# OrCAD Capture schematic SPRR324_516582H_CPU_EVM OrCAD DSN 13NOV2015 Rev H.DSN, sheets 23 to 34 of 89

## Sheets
23 SH29 - VAYU VIDEO PORTS IN: size B; rev: A
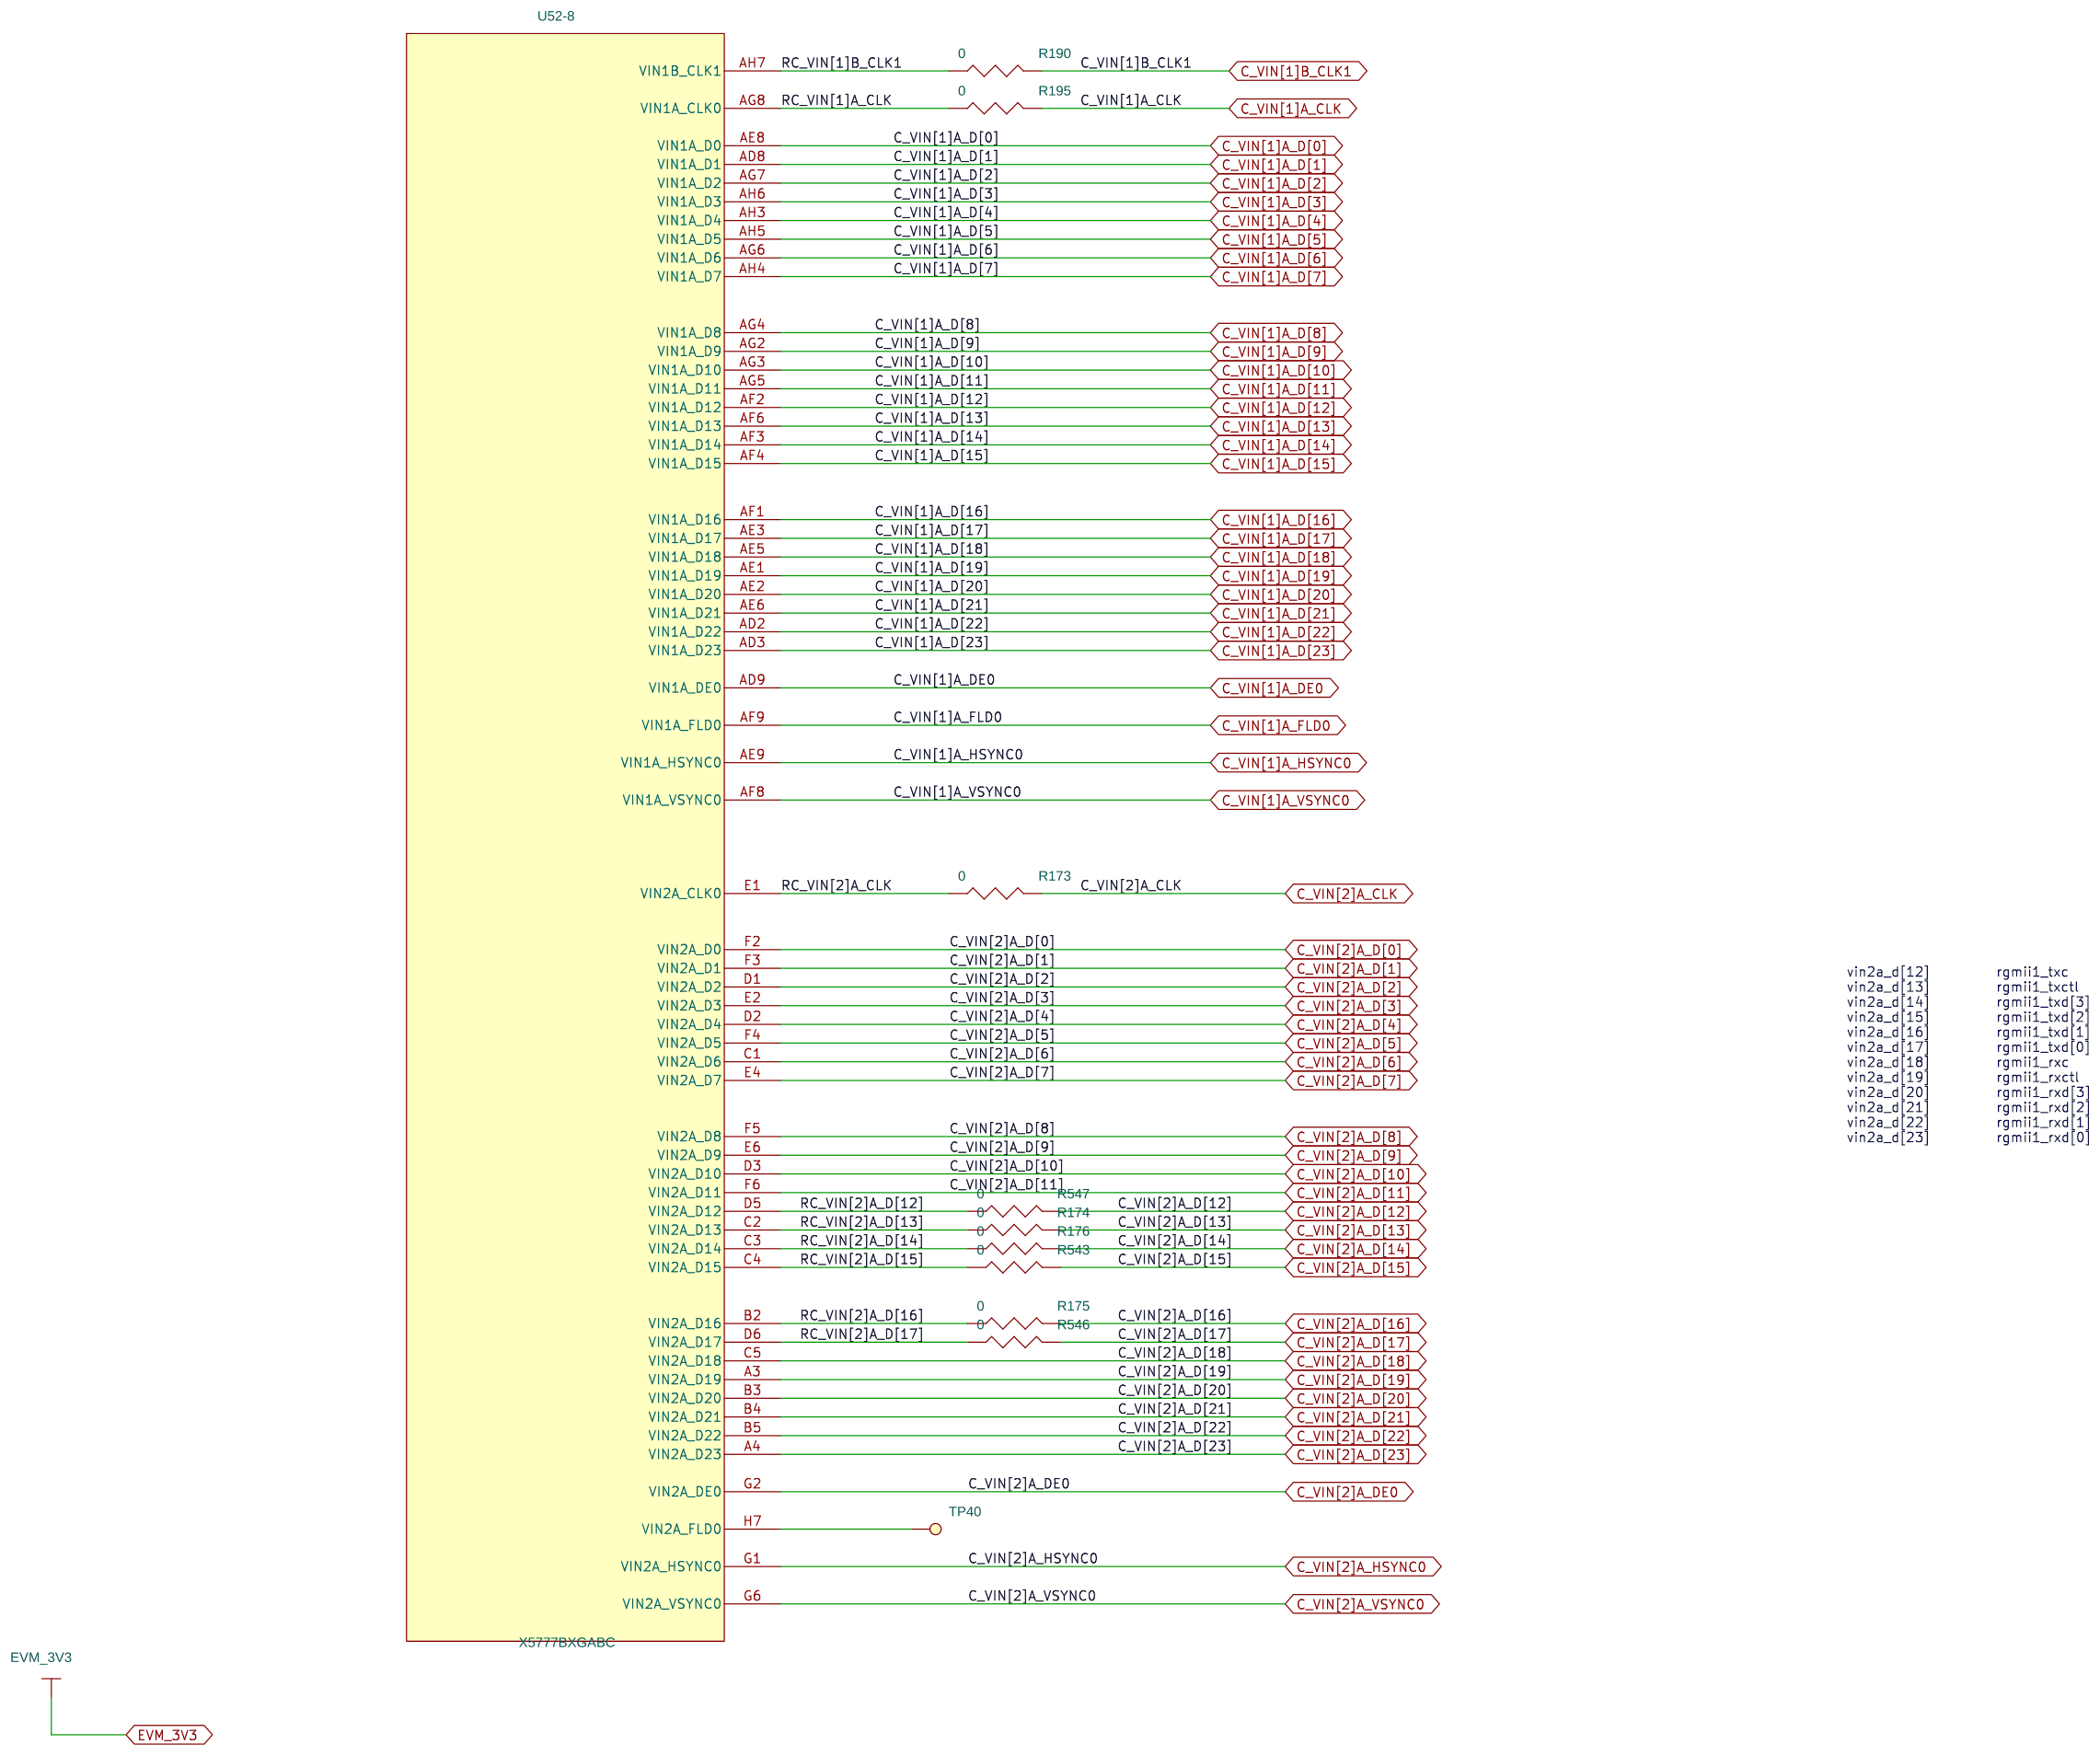
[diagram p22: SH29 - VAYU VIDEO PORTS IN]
24 SH30 - VIN1 MUX: size B; rev: A
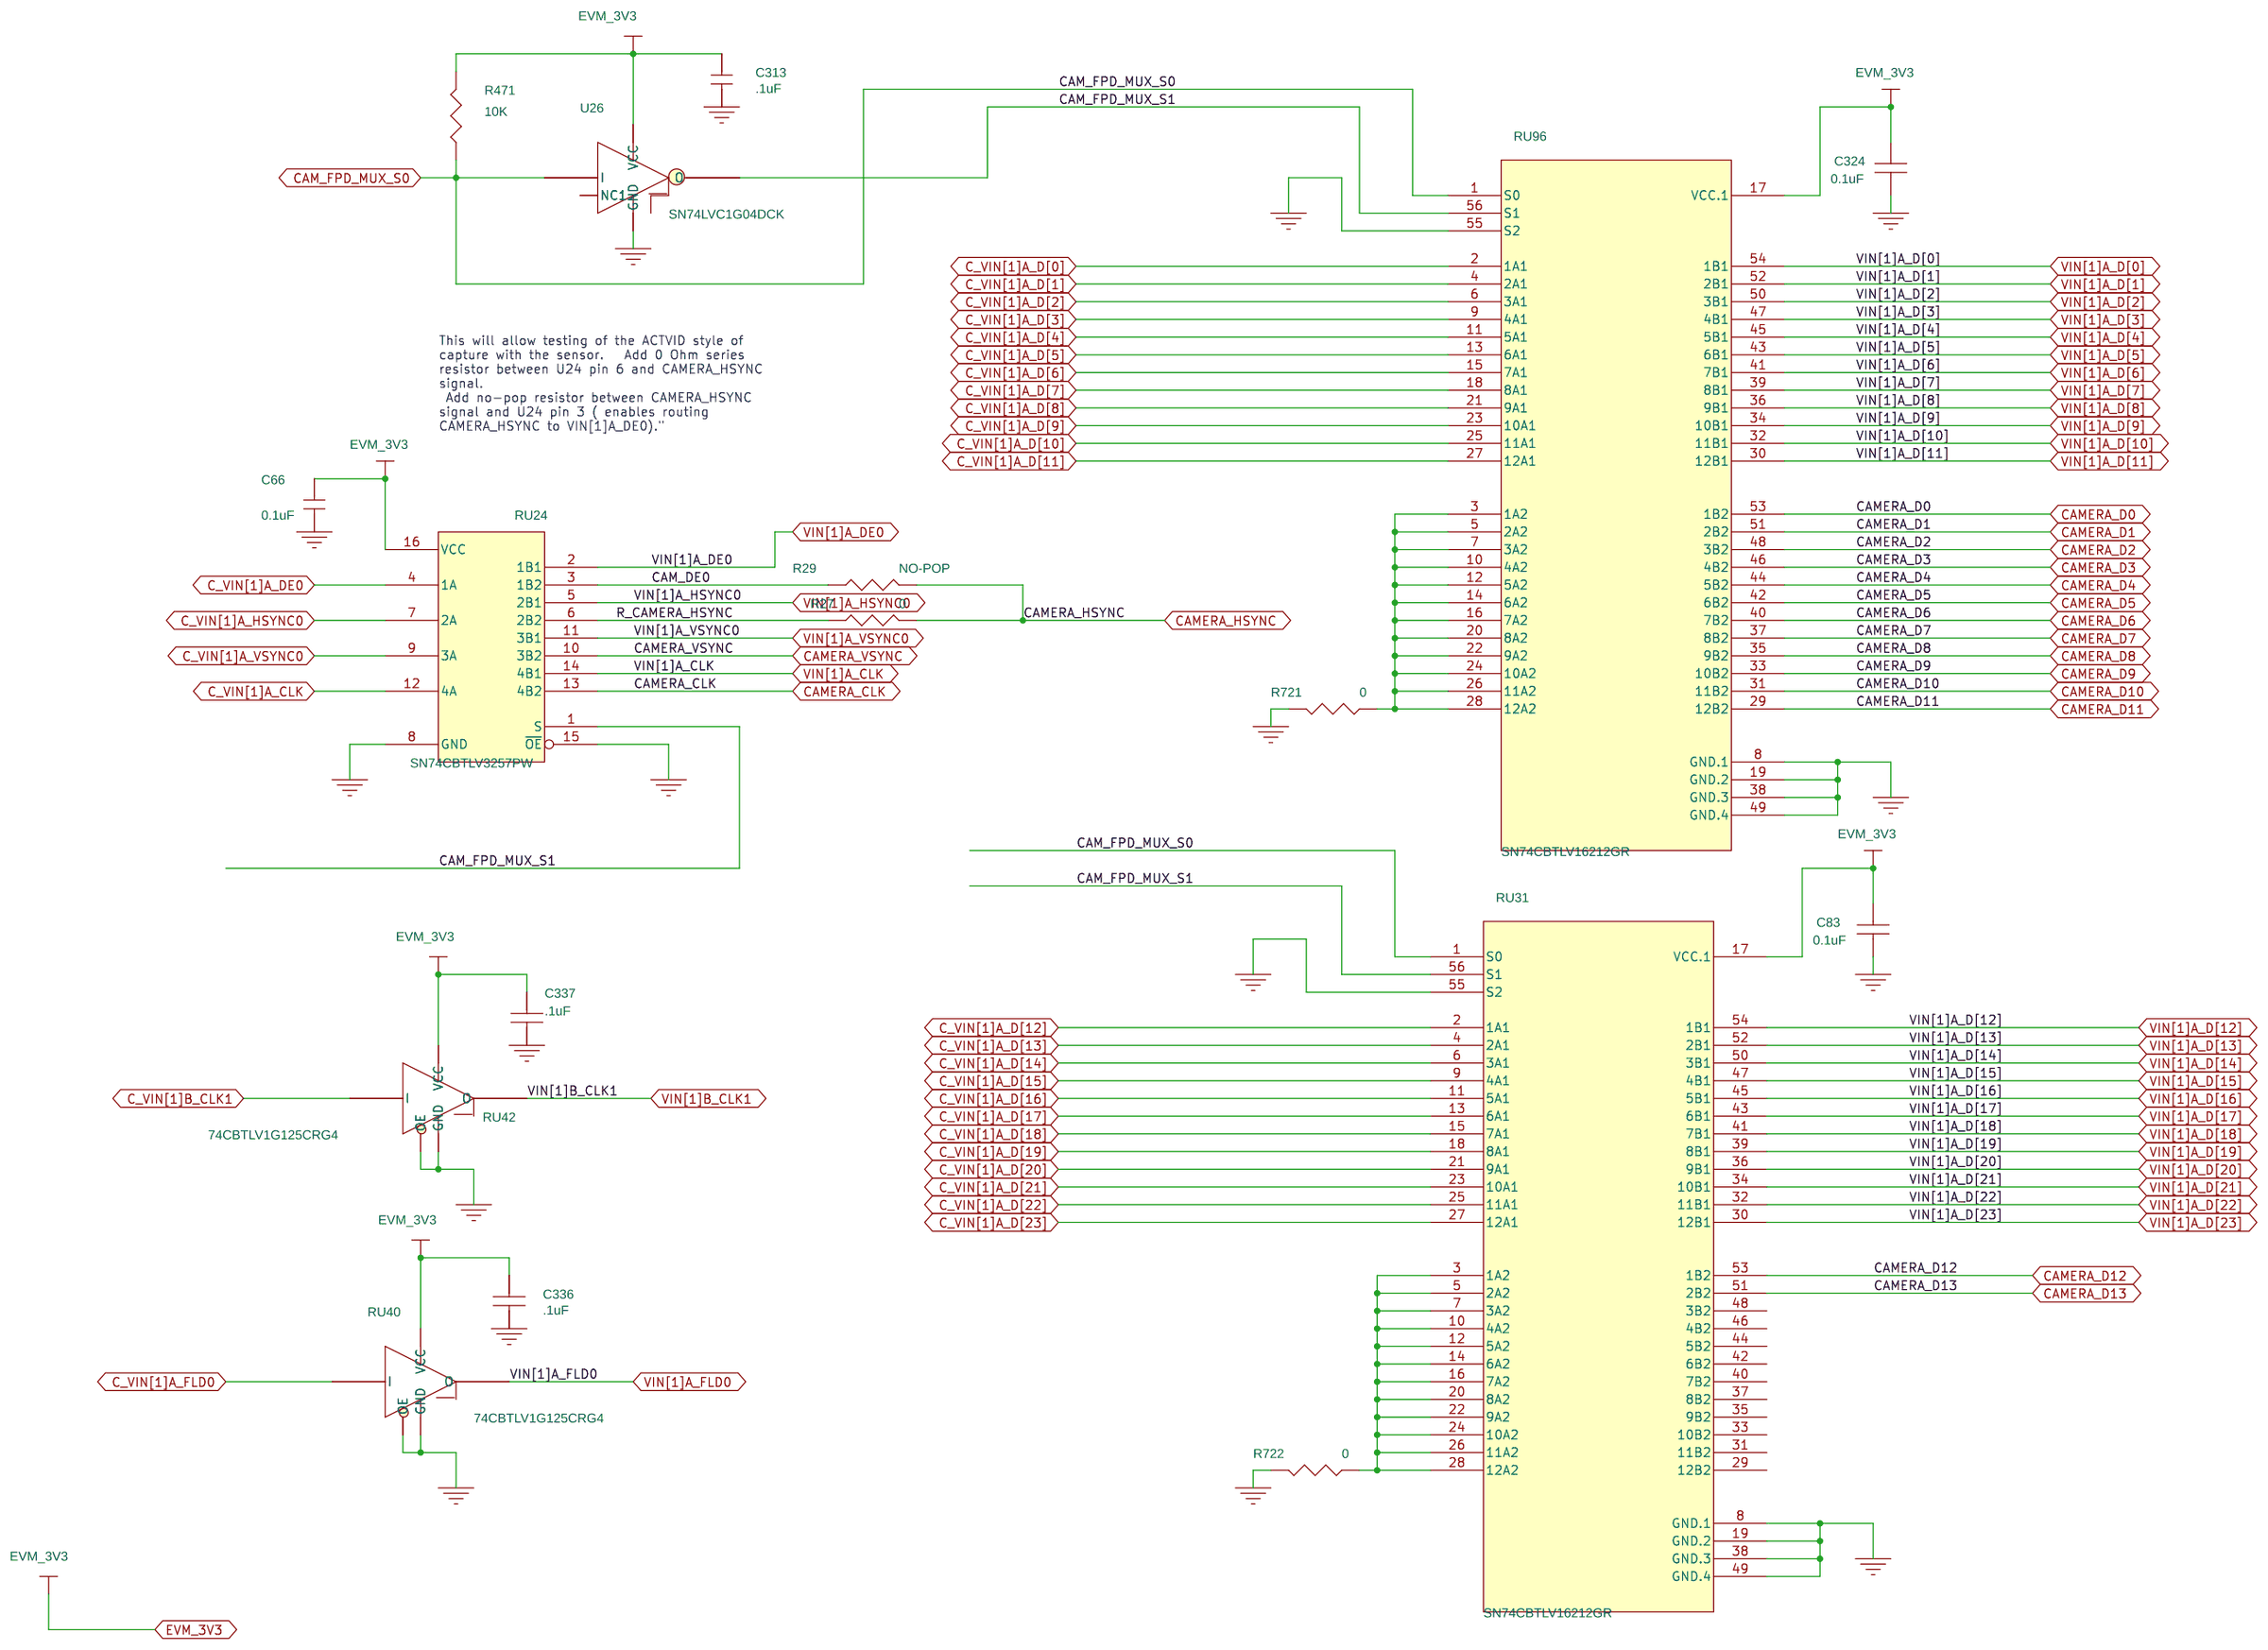
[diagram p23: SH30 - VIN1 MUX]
25 SH31 - VIN2 MUX: size B; rev: C
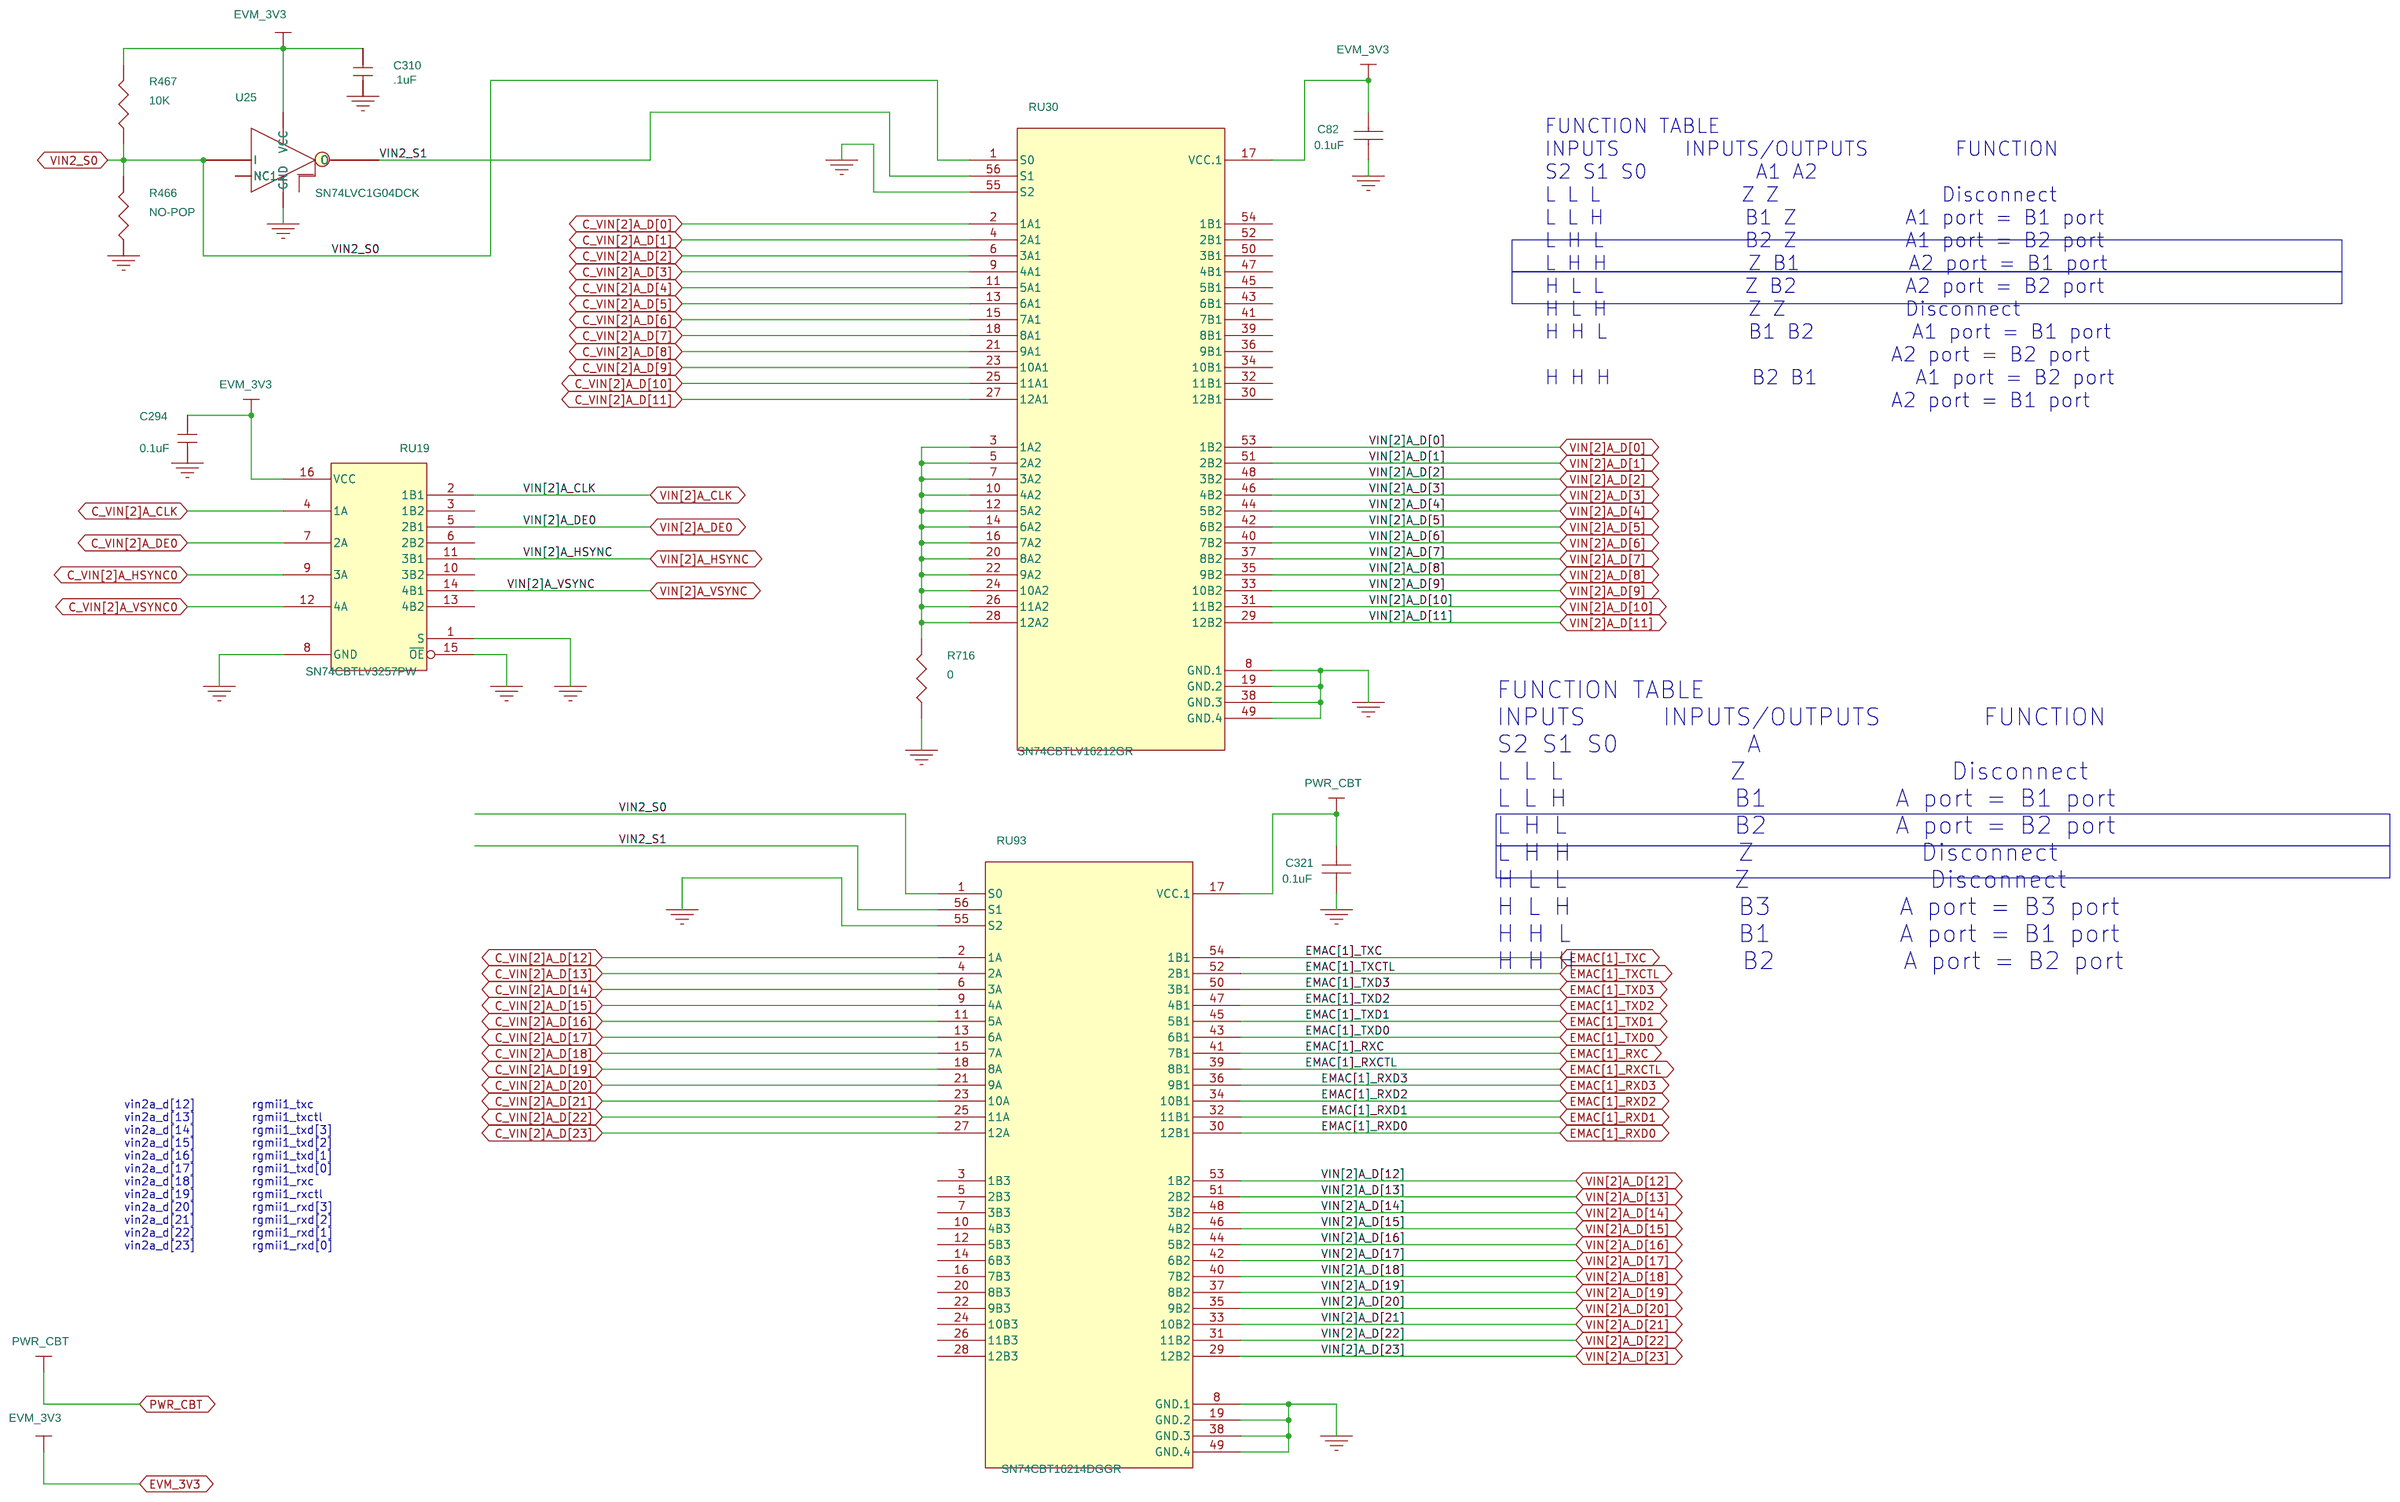
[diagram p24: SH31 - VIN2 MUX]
26 SH32 - LCD CONNECTOR: size B; rev: A
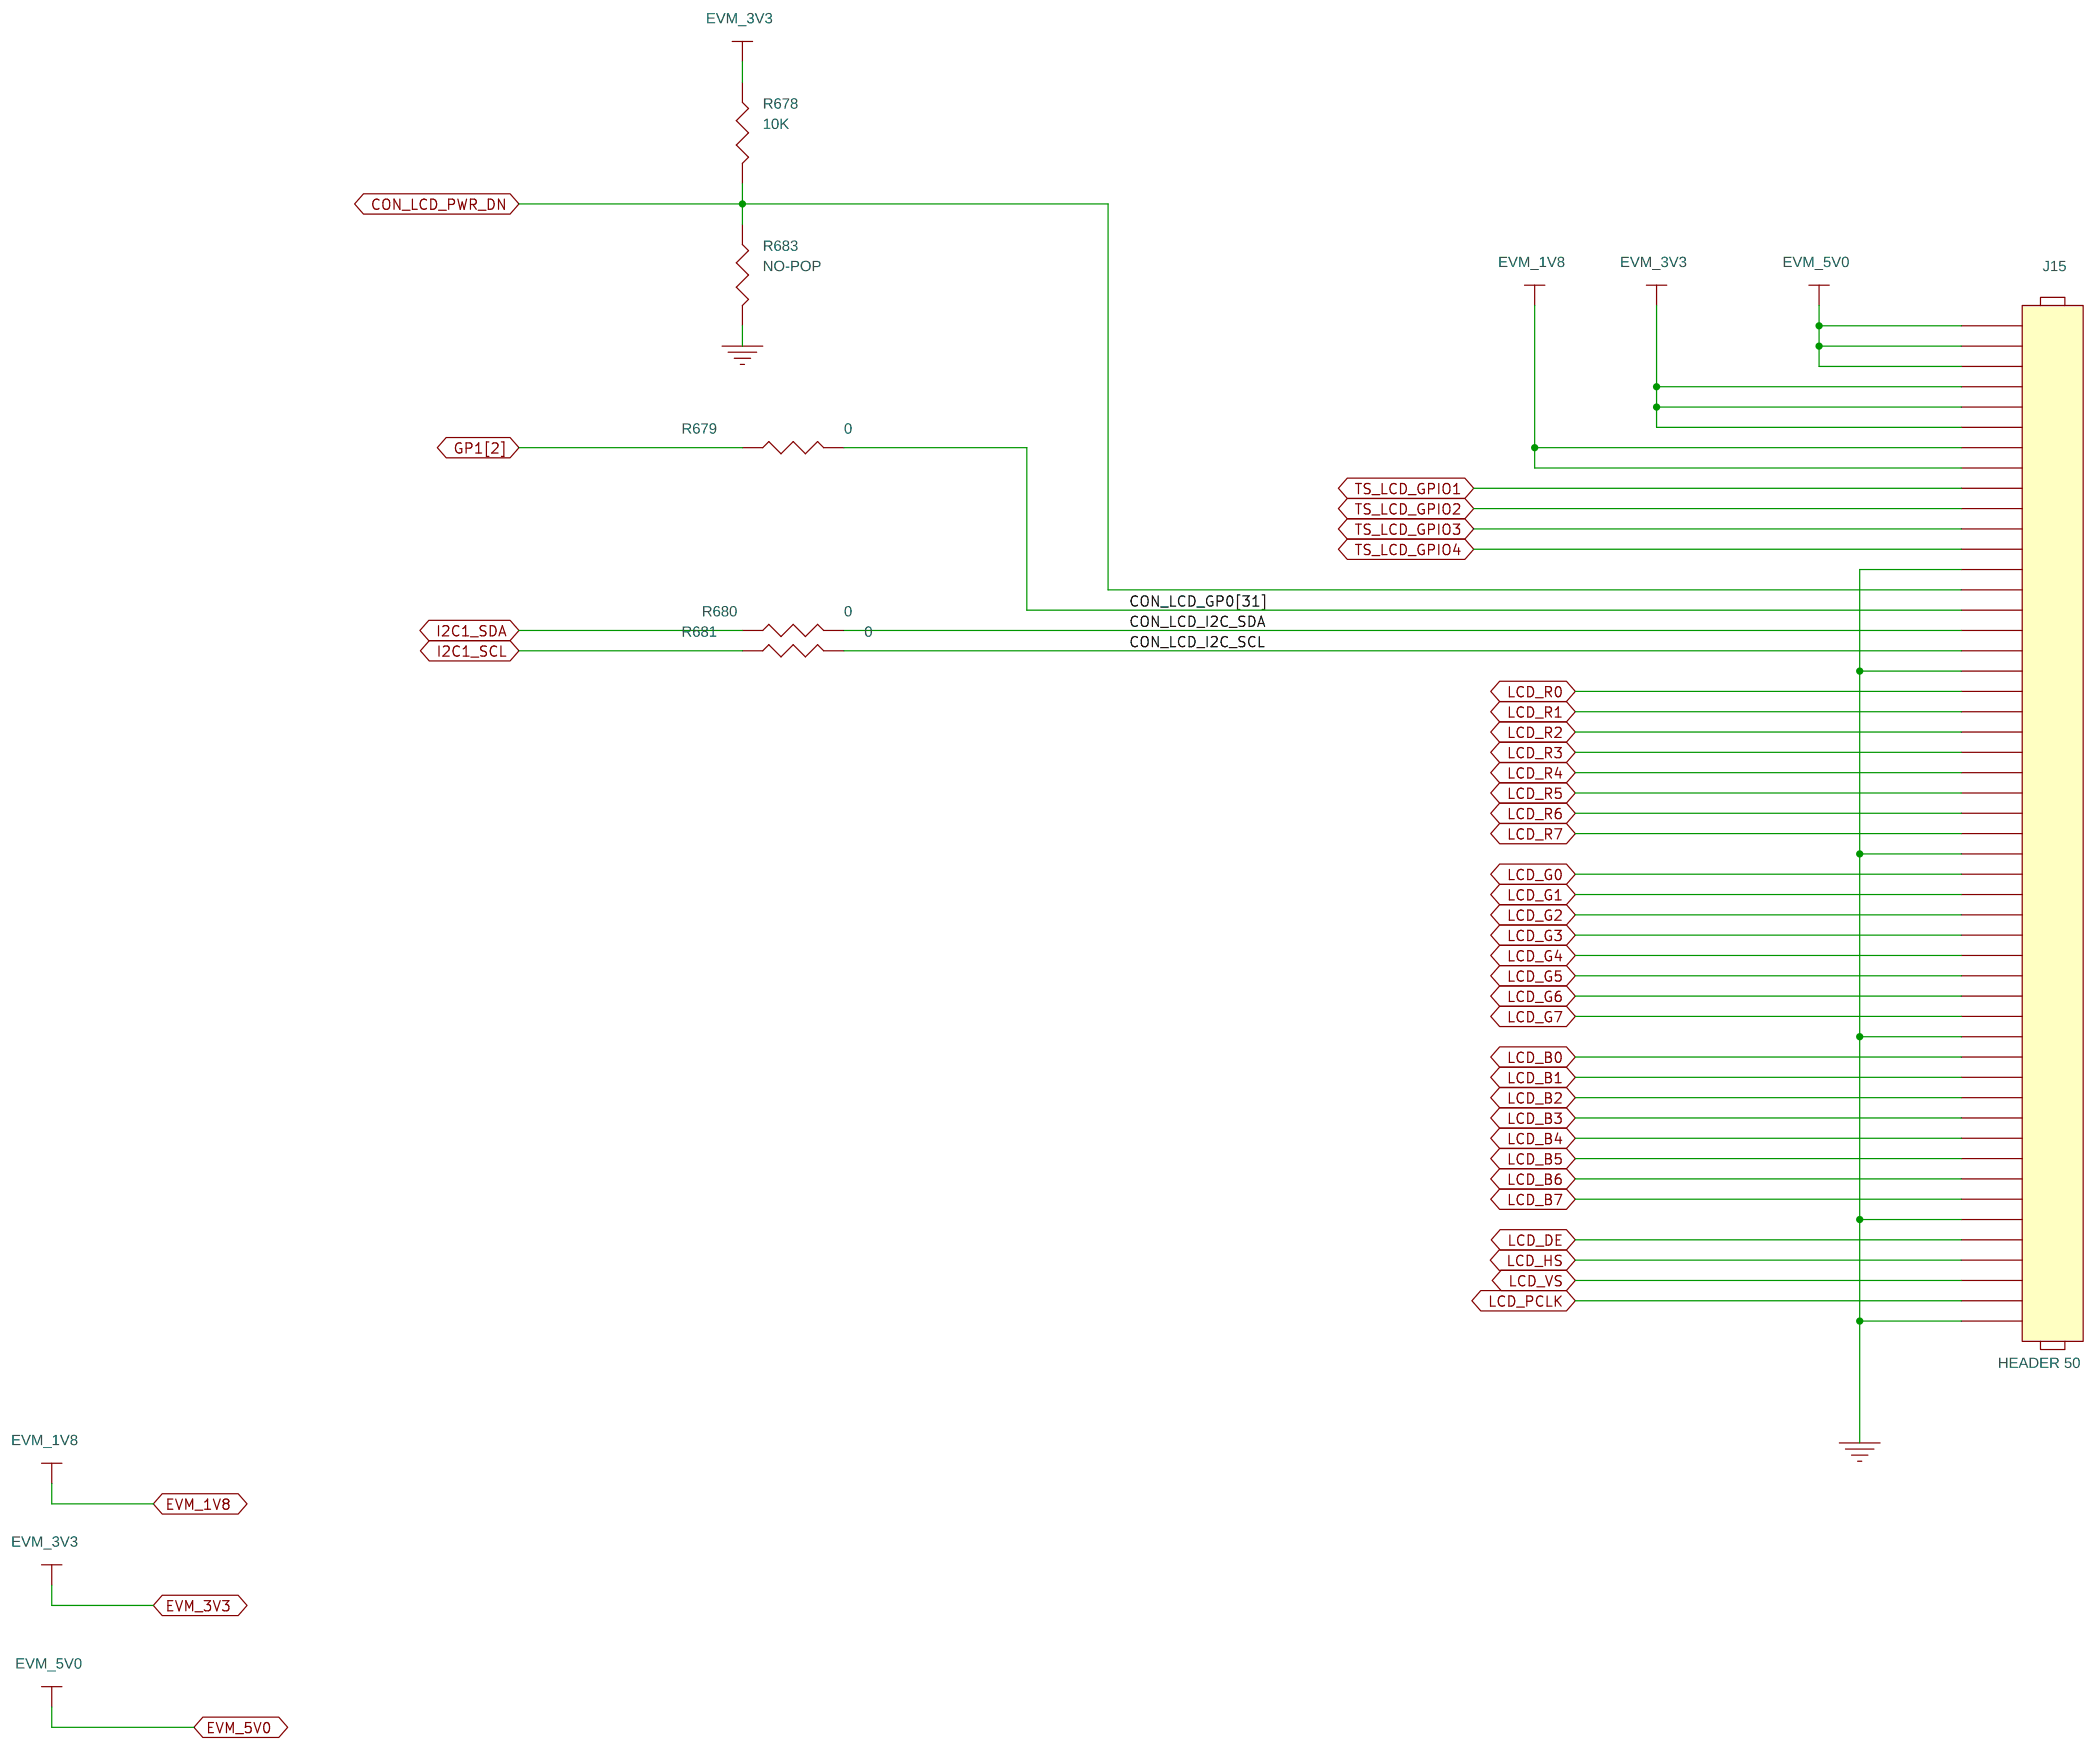
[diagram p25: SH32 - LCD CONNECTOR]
27 SH33 - HDMI OUTPUT CONNECTOR: size B
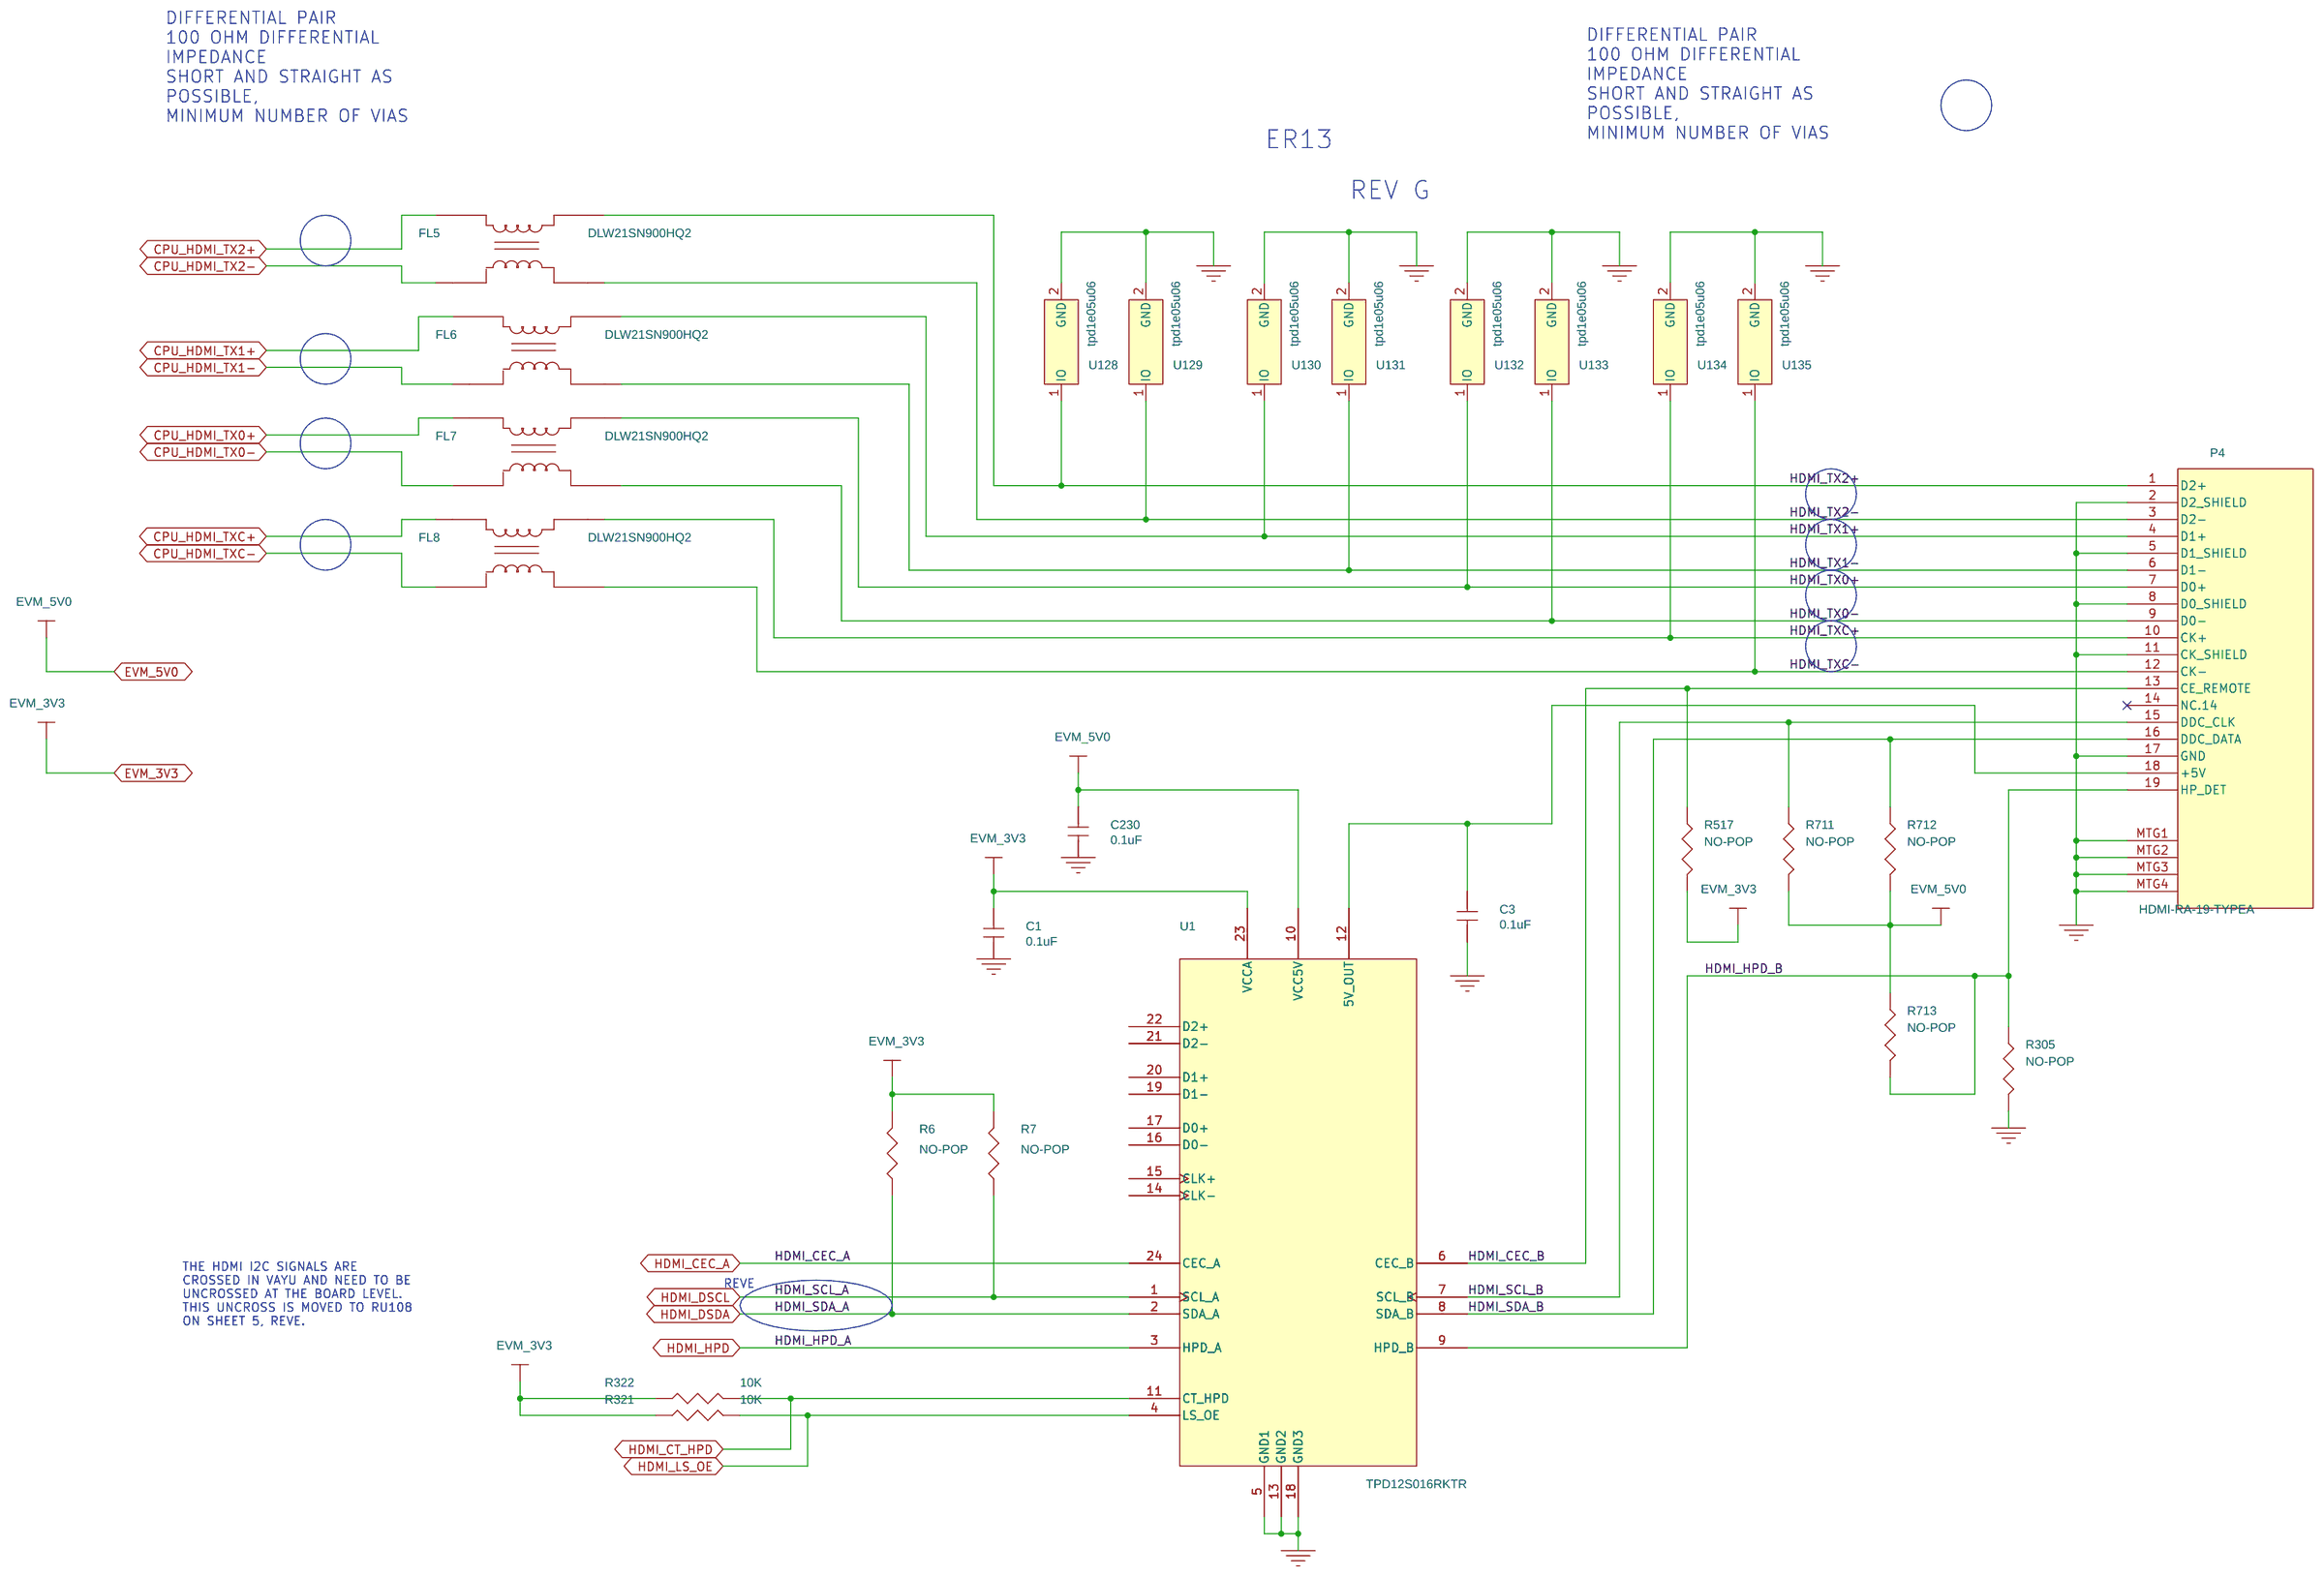
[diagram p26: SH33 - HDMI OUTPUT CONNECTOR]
28 SH34 - FPD LINK: size B; rev: E
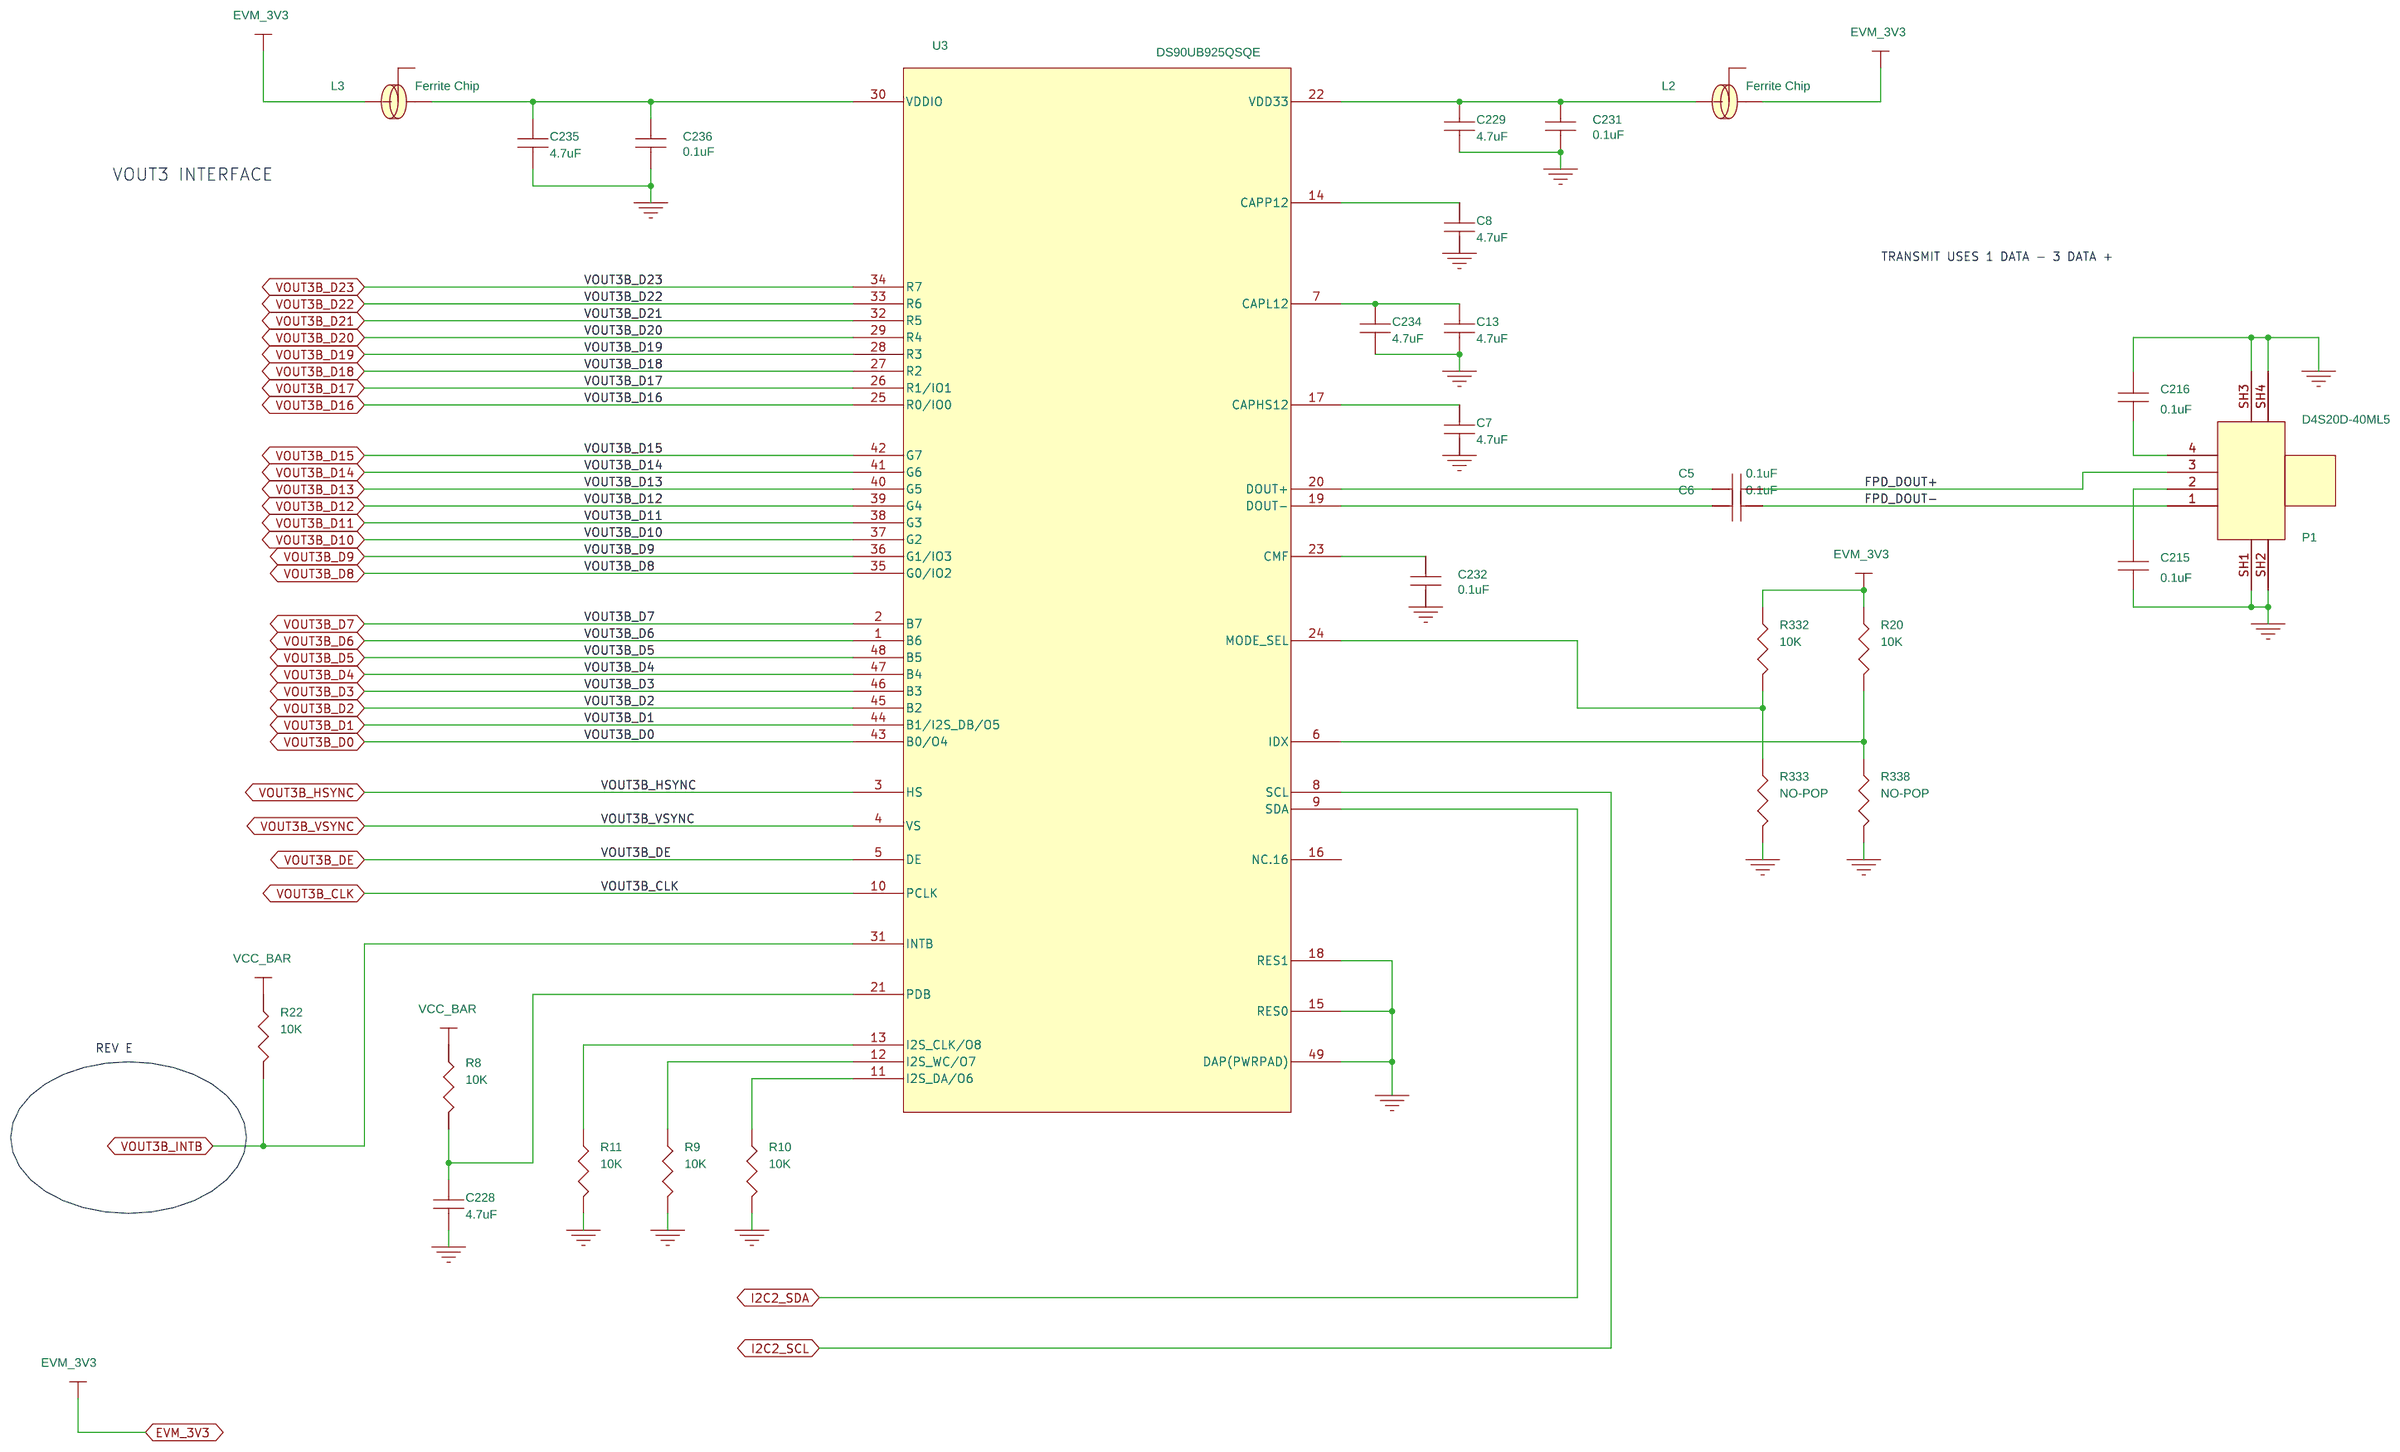
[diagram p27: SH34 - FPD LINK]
29 SH35 - CAMERA IF: size B; rev: G
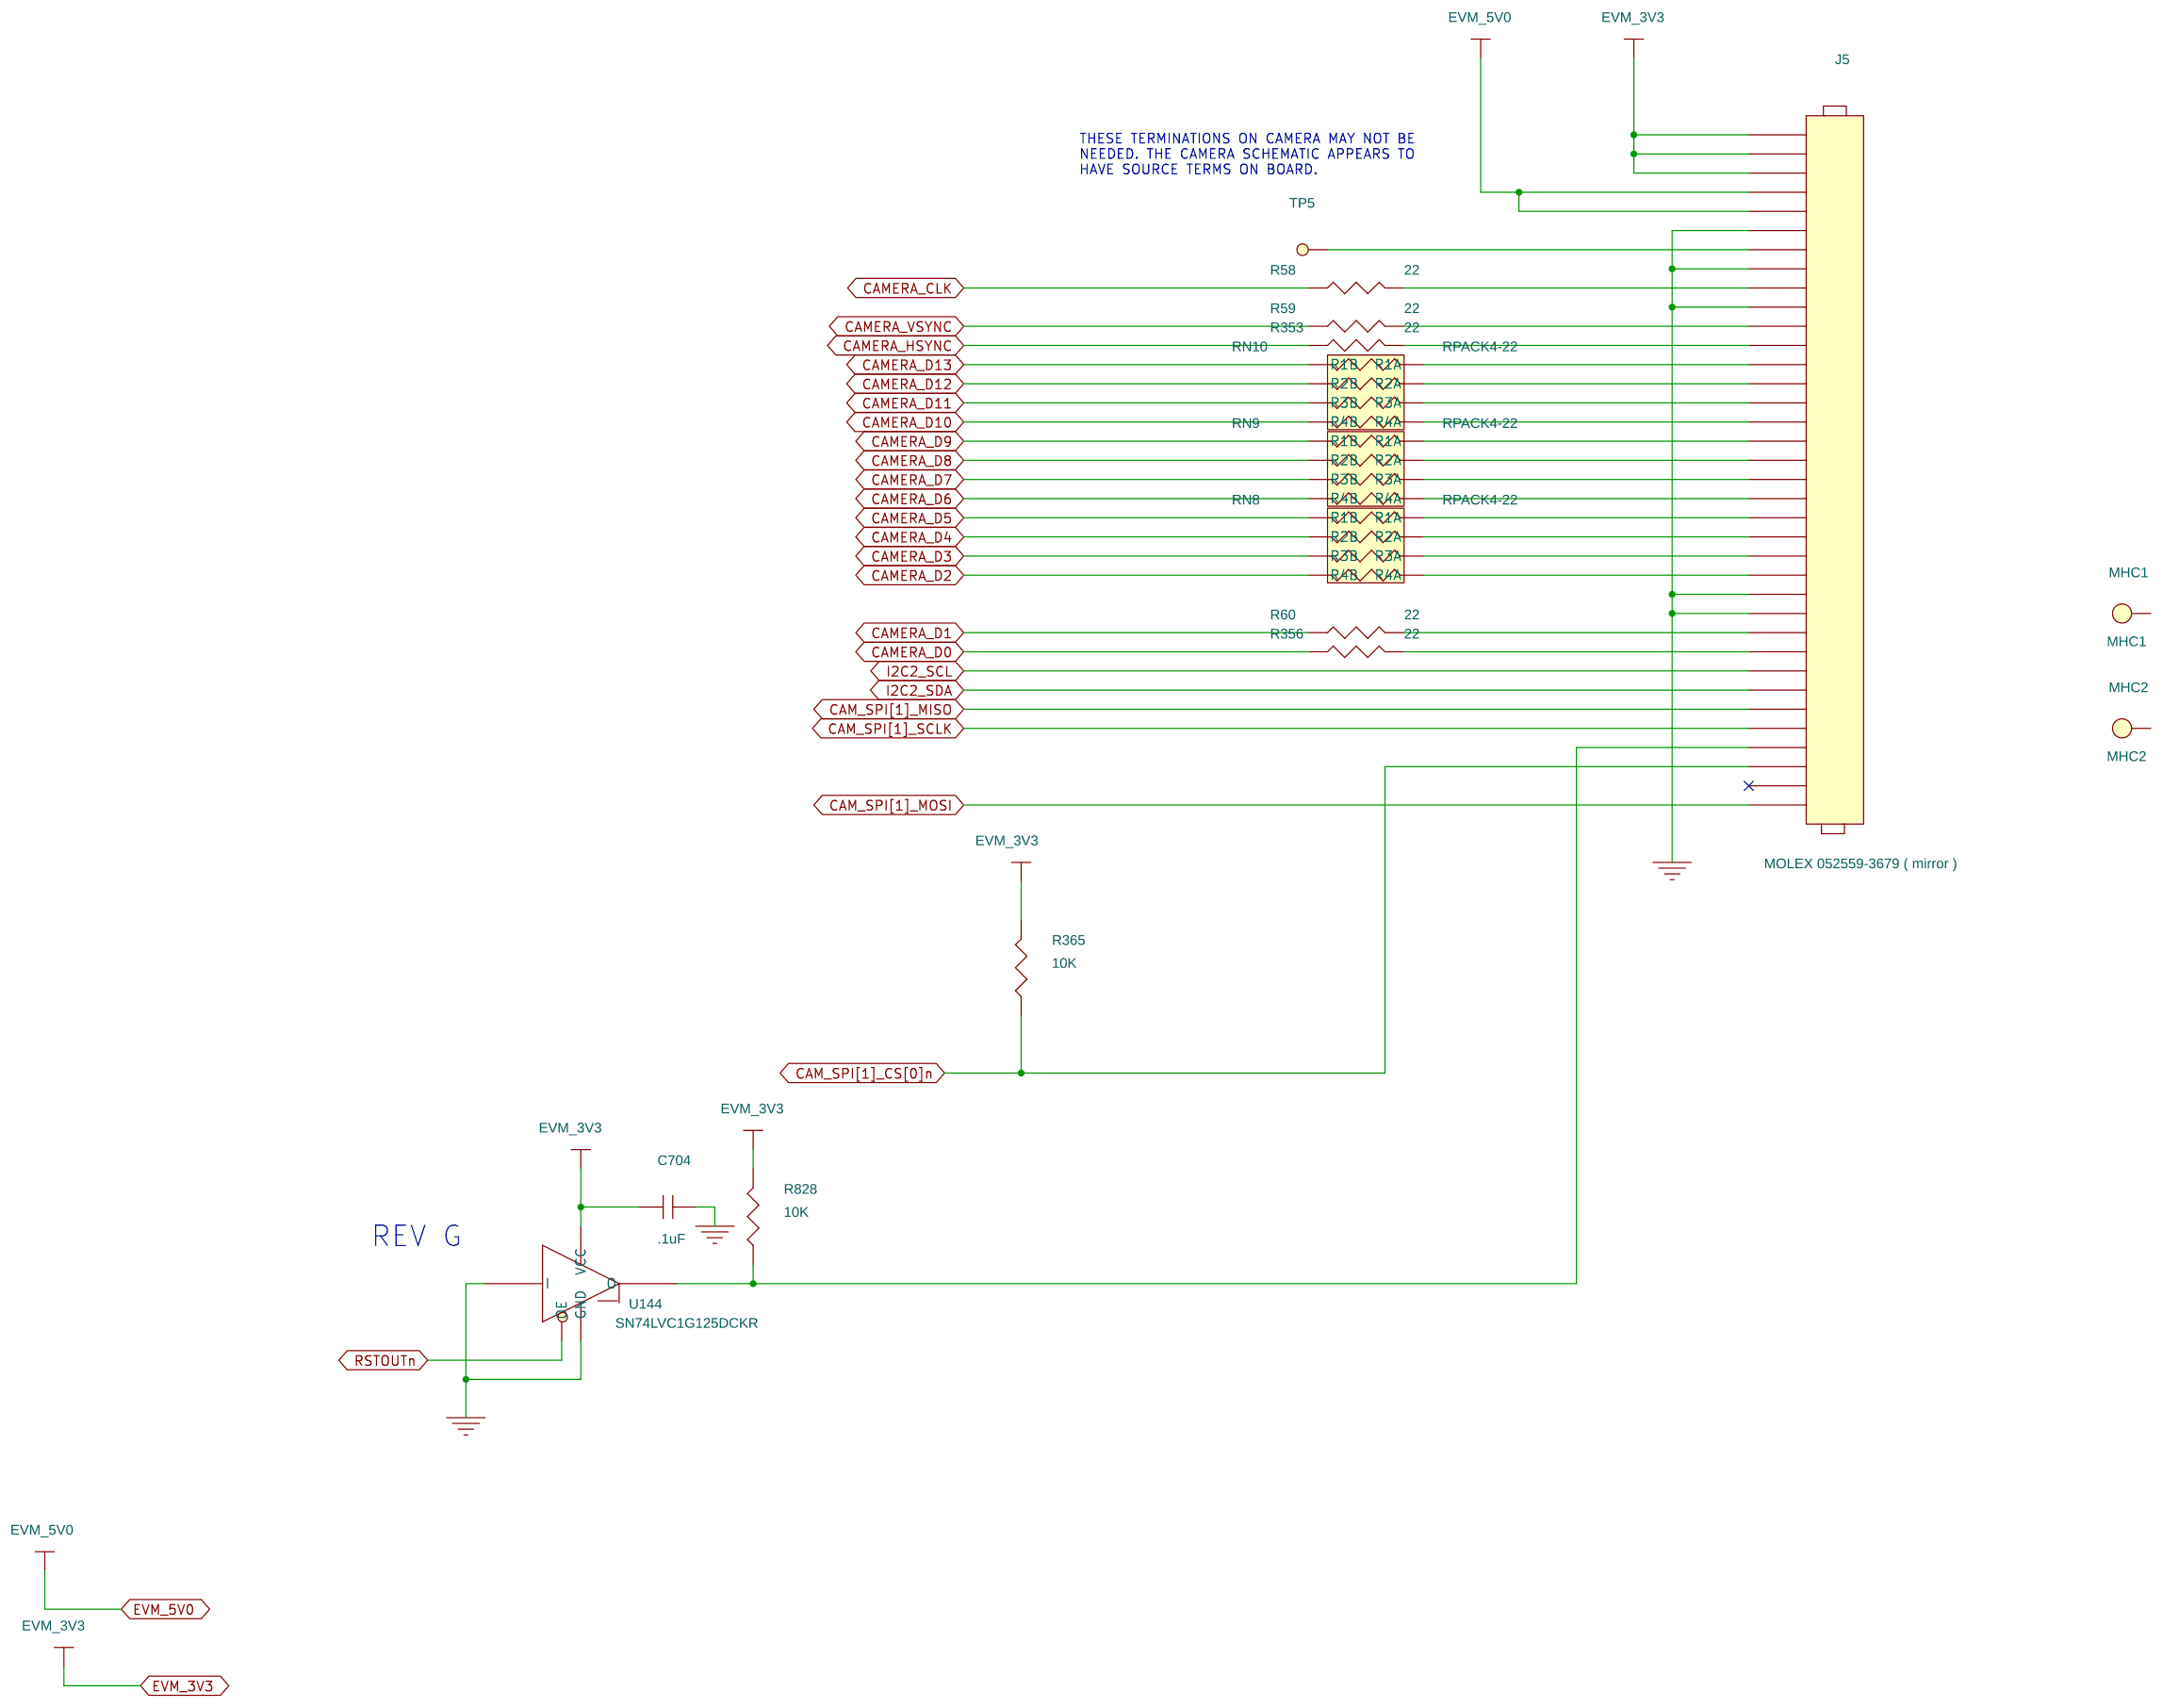
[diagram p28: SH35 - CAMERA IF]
30 SH36 - SERDES CLOCK: size B; rev: A
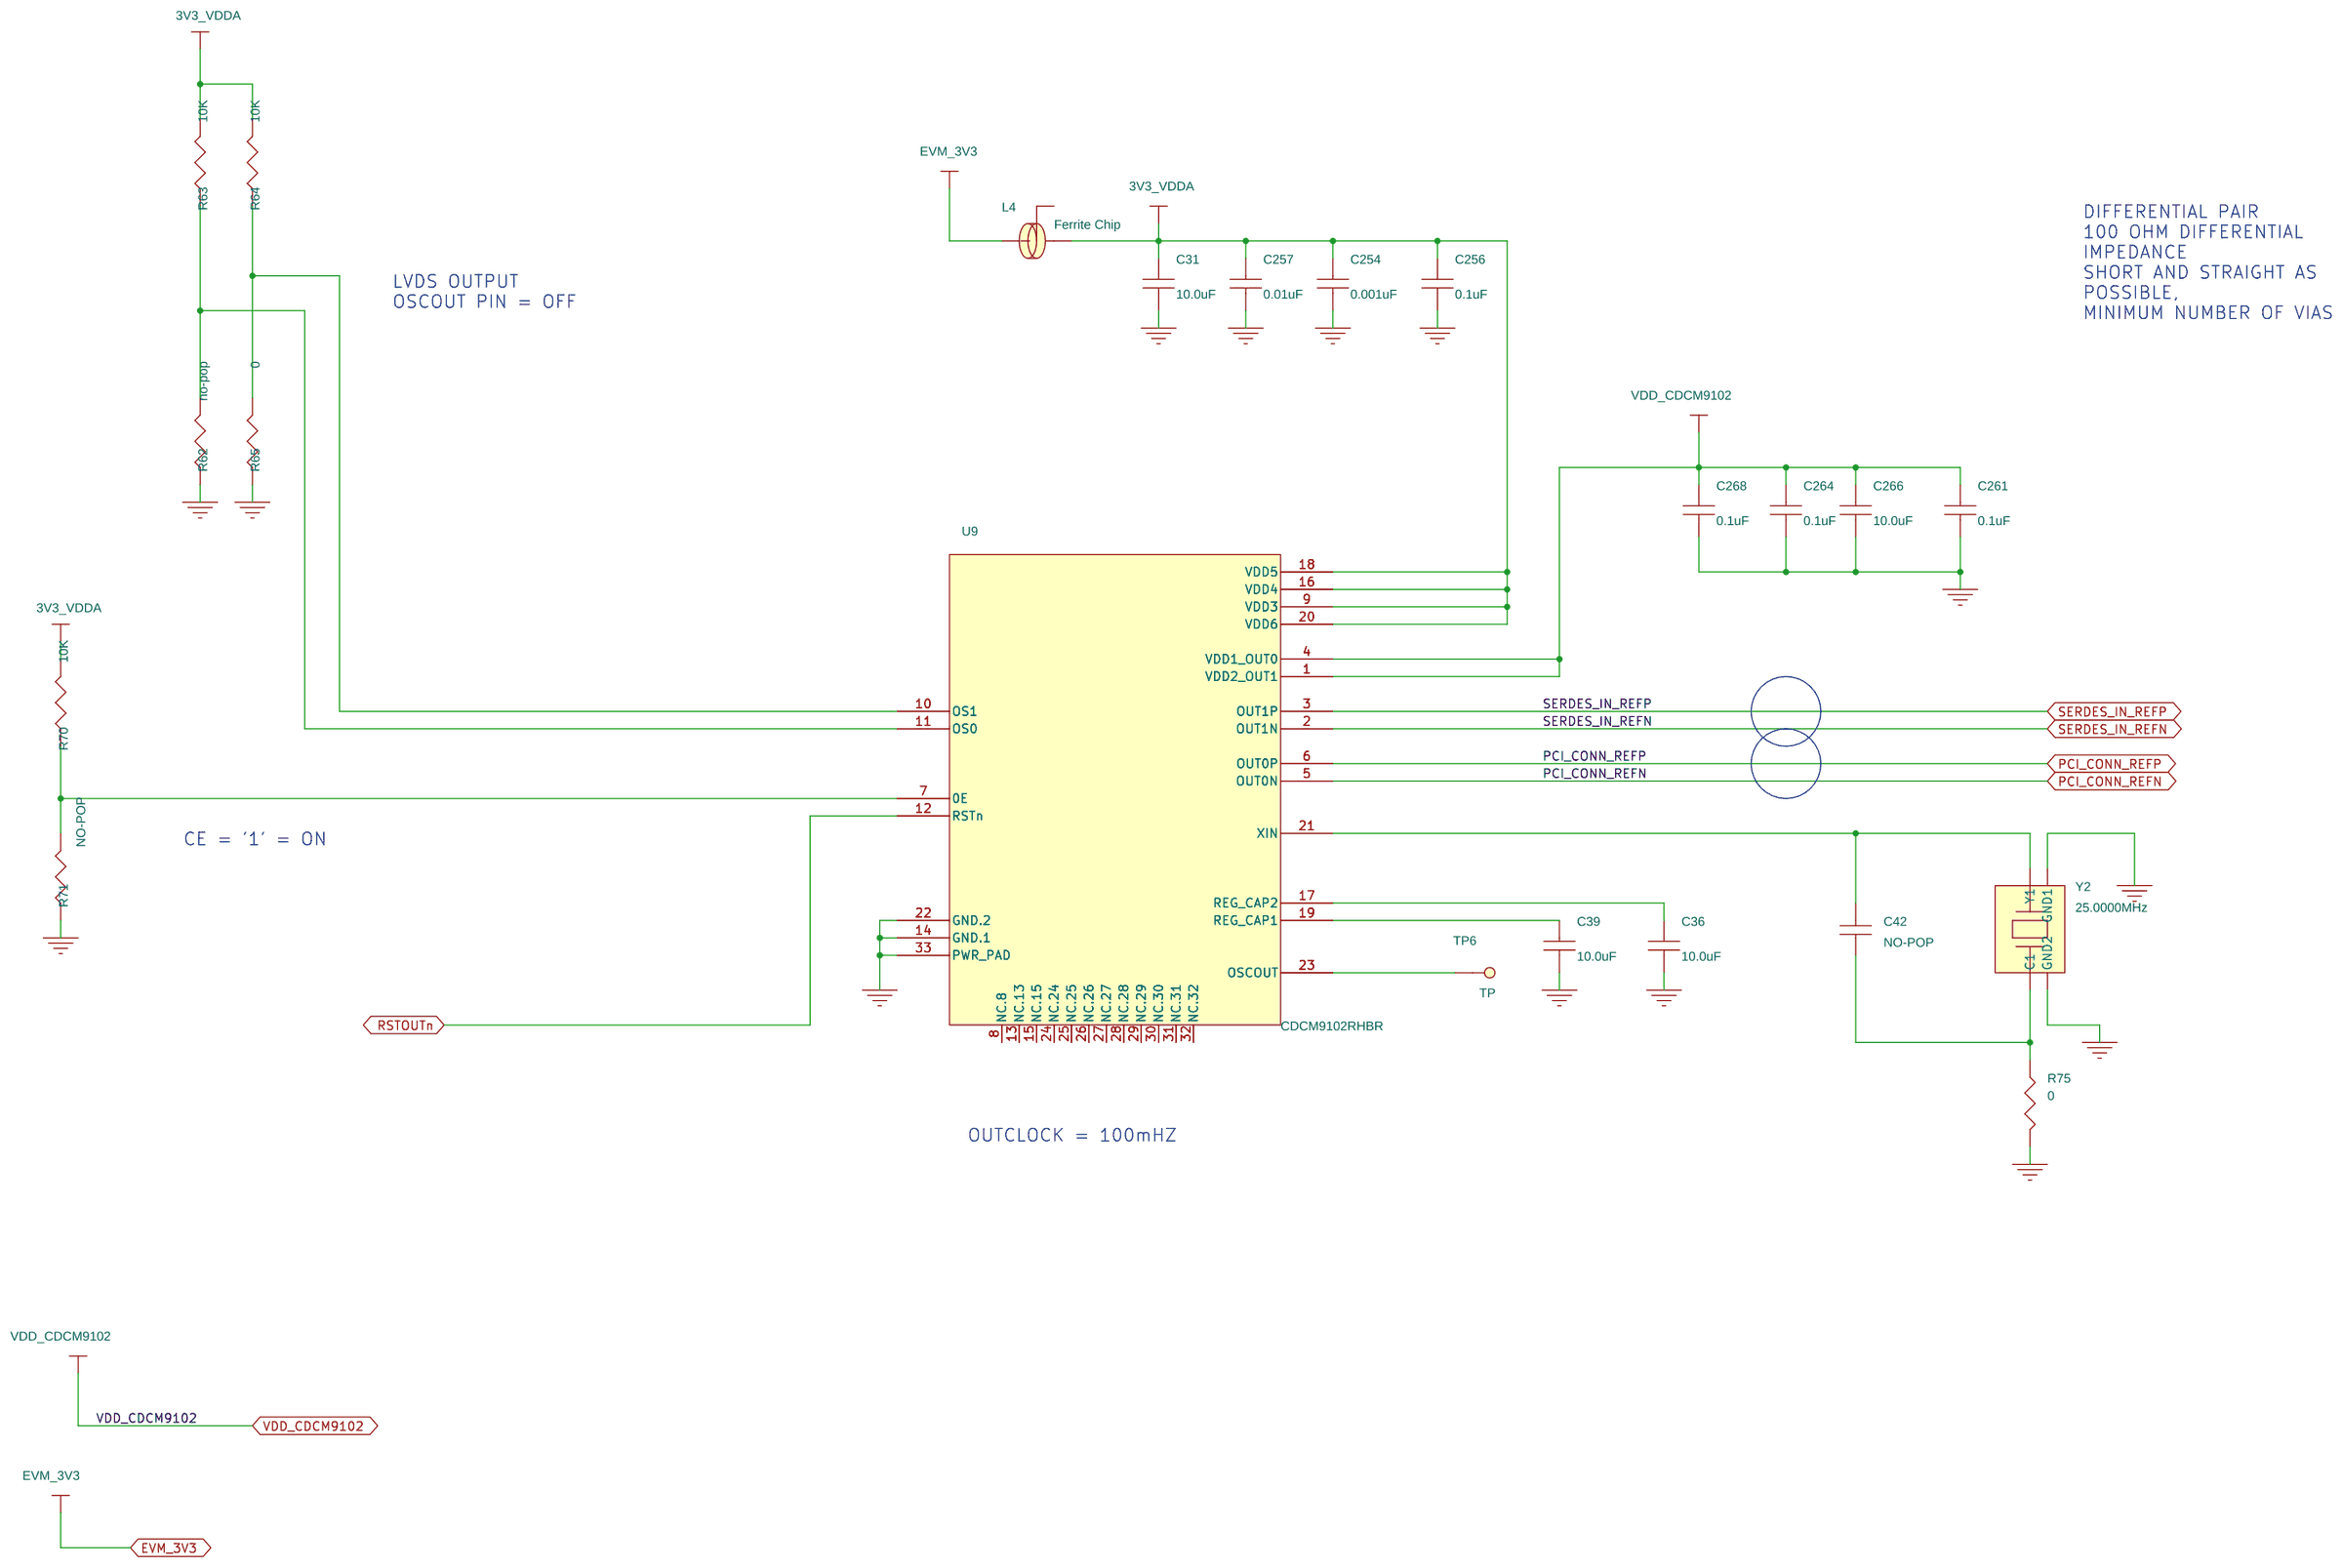
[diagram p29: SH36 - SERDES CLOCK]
31 SH38 - PCIe CONNECTORS: size B; rev: A
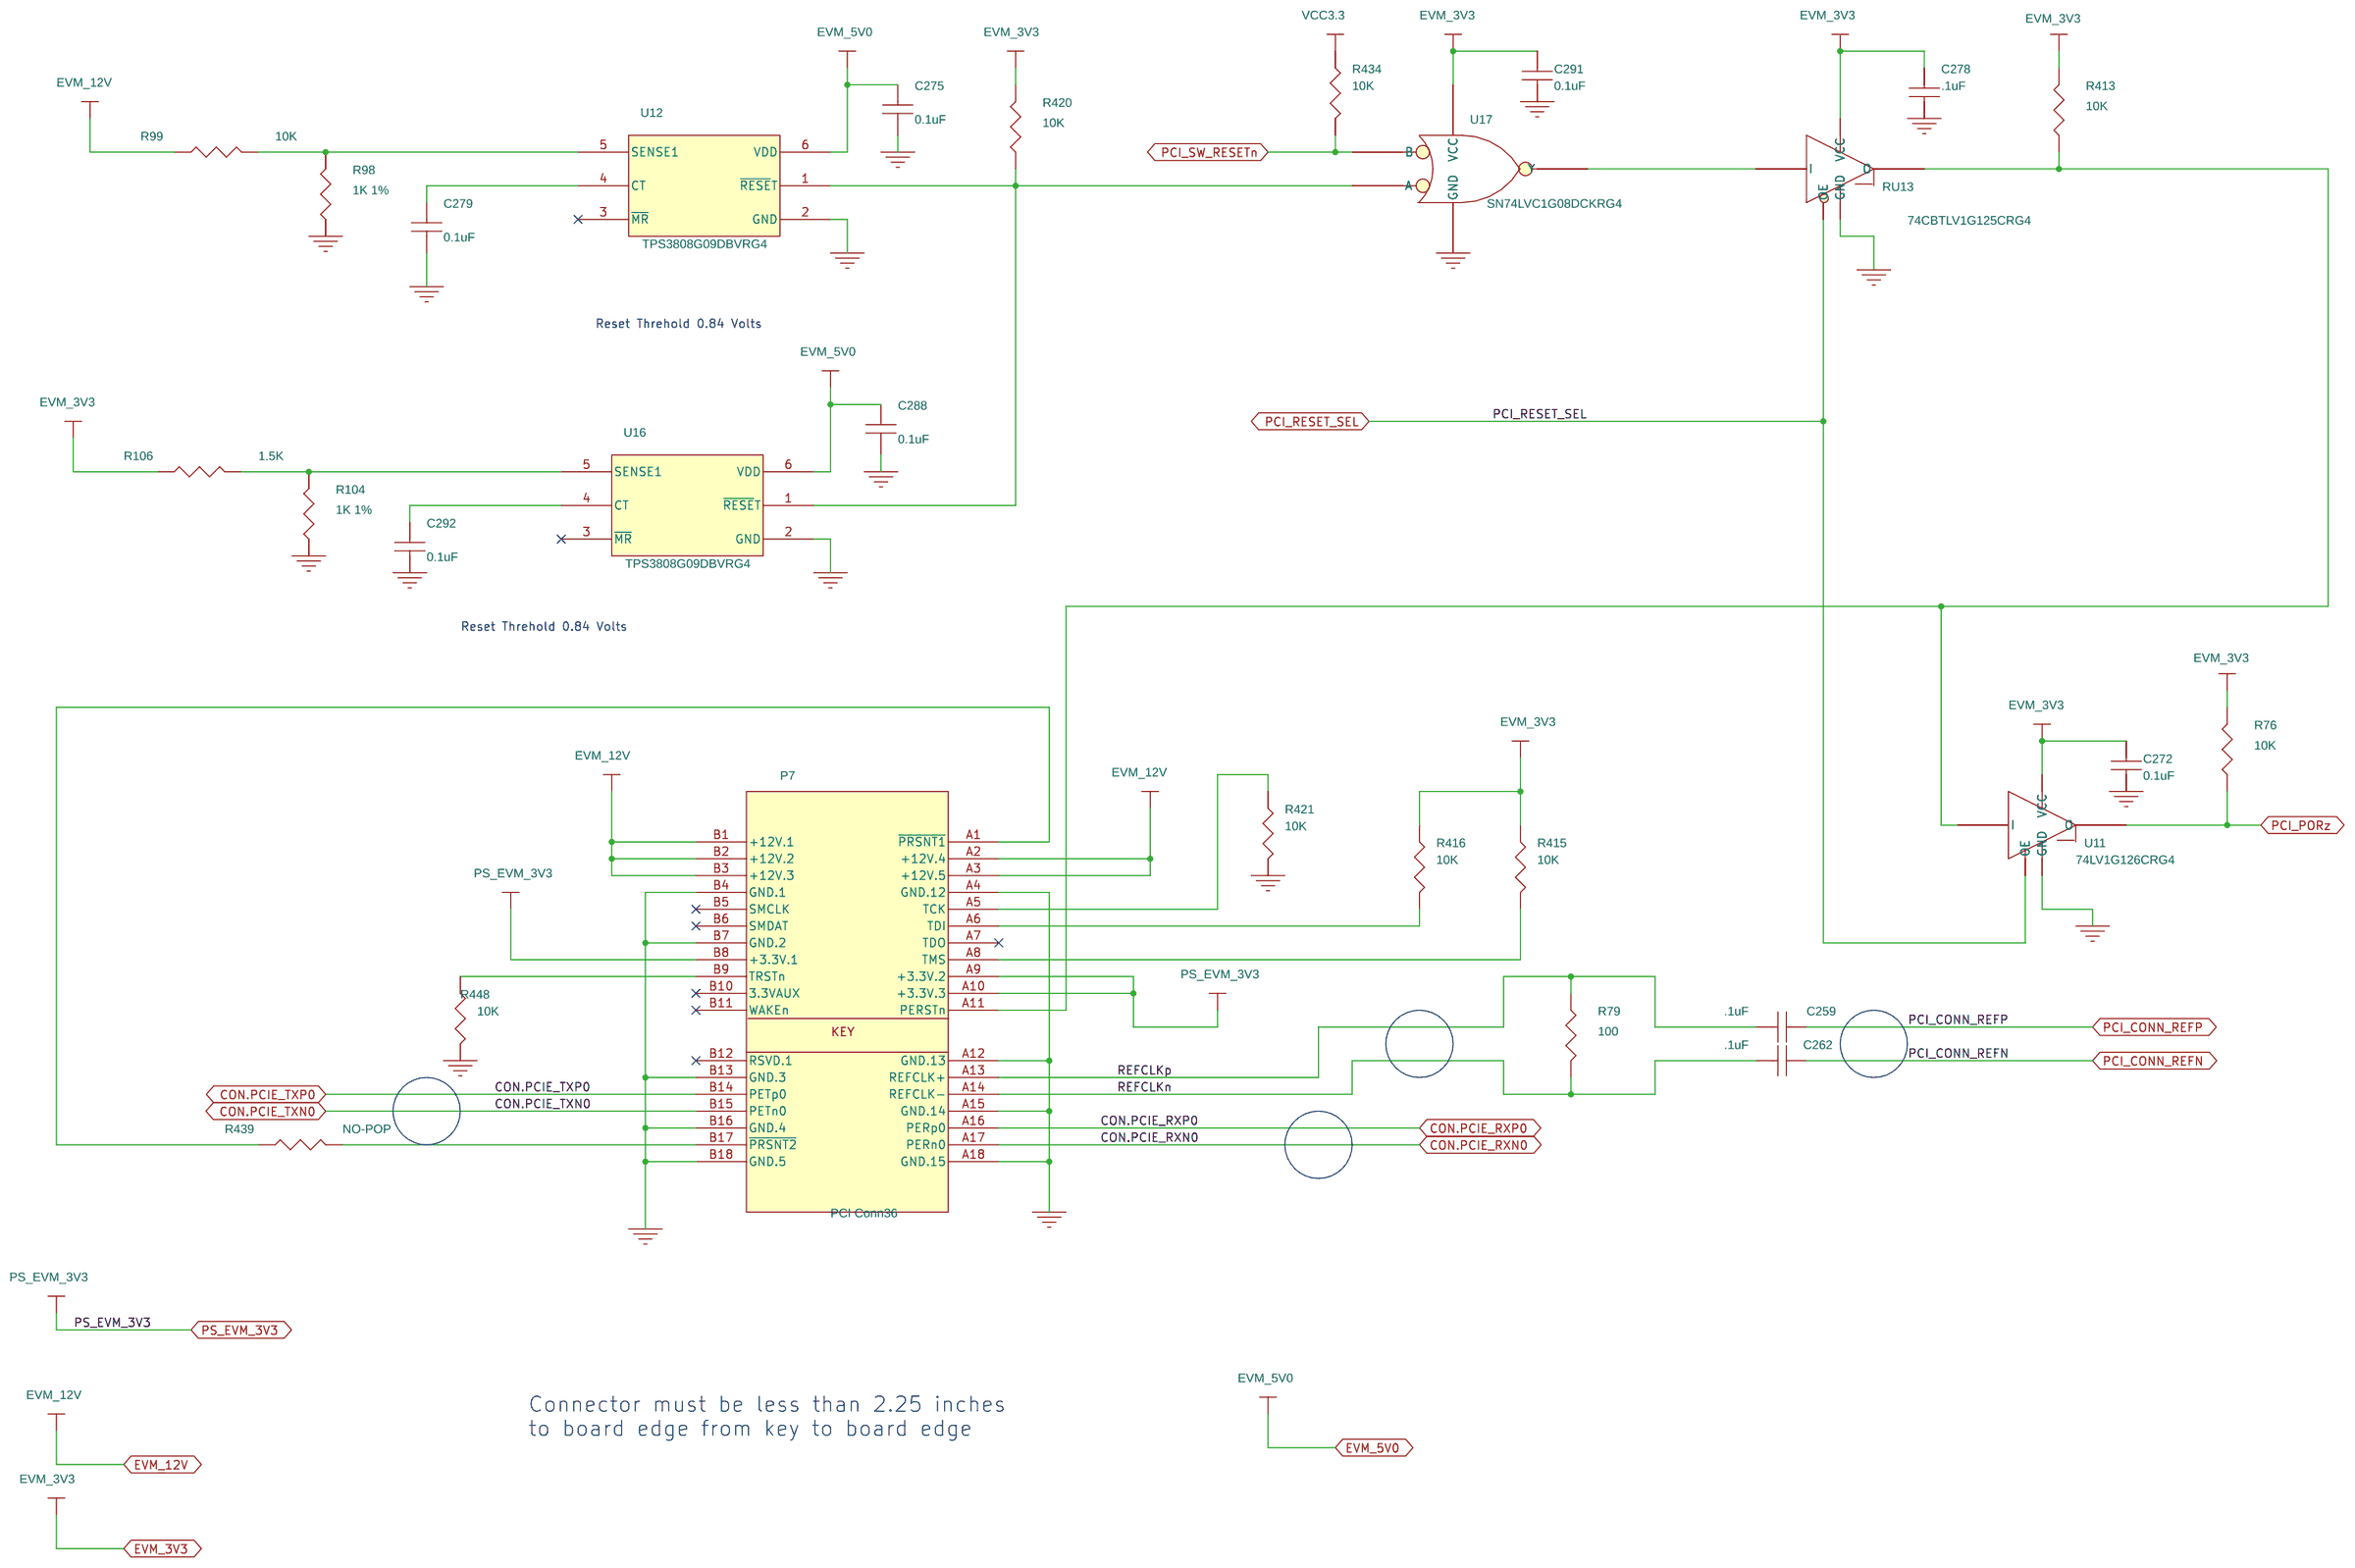
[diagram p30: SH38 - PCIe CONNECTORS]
32 SH39 - VAYU JTAG: size B
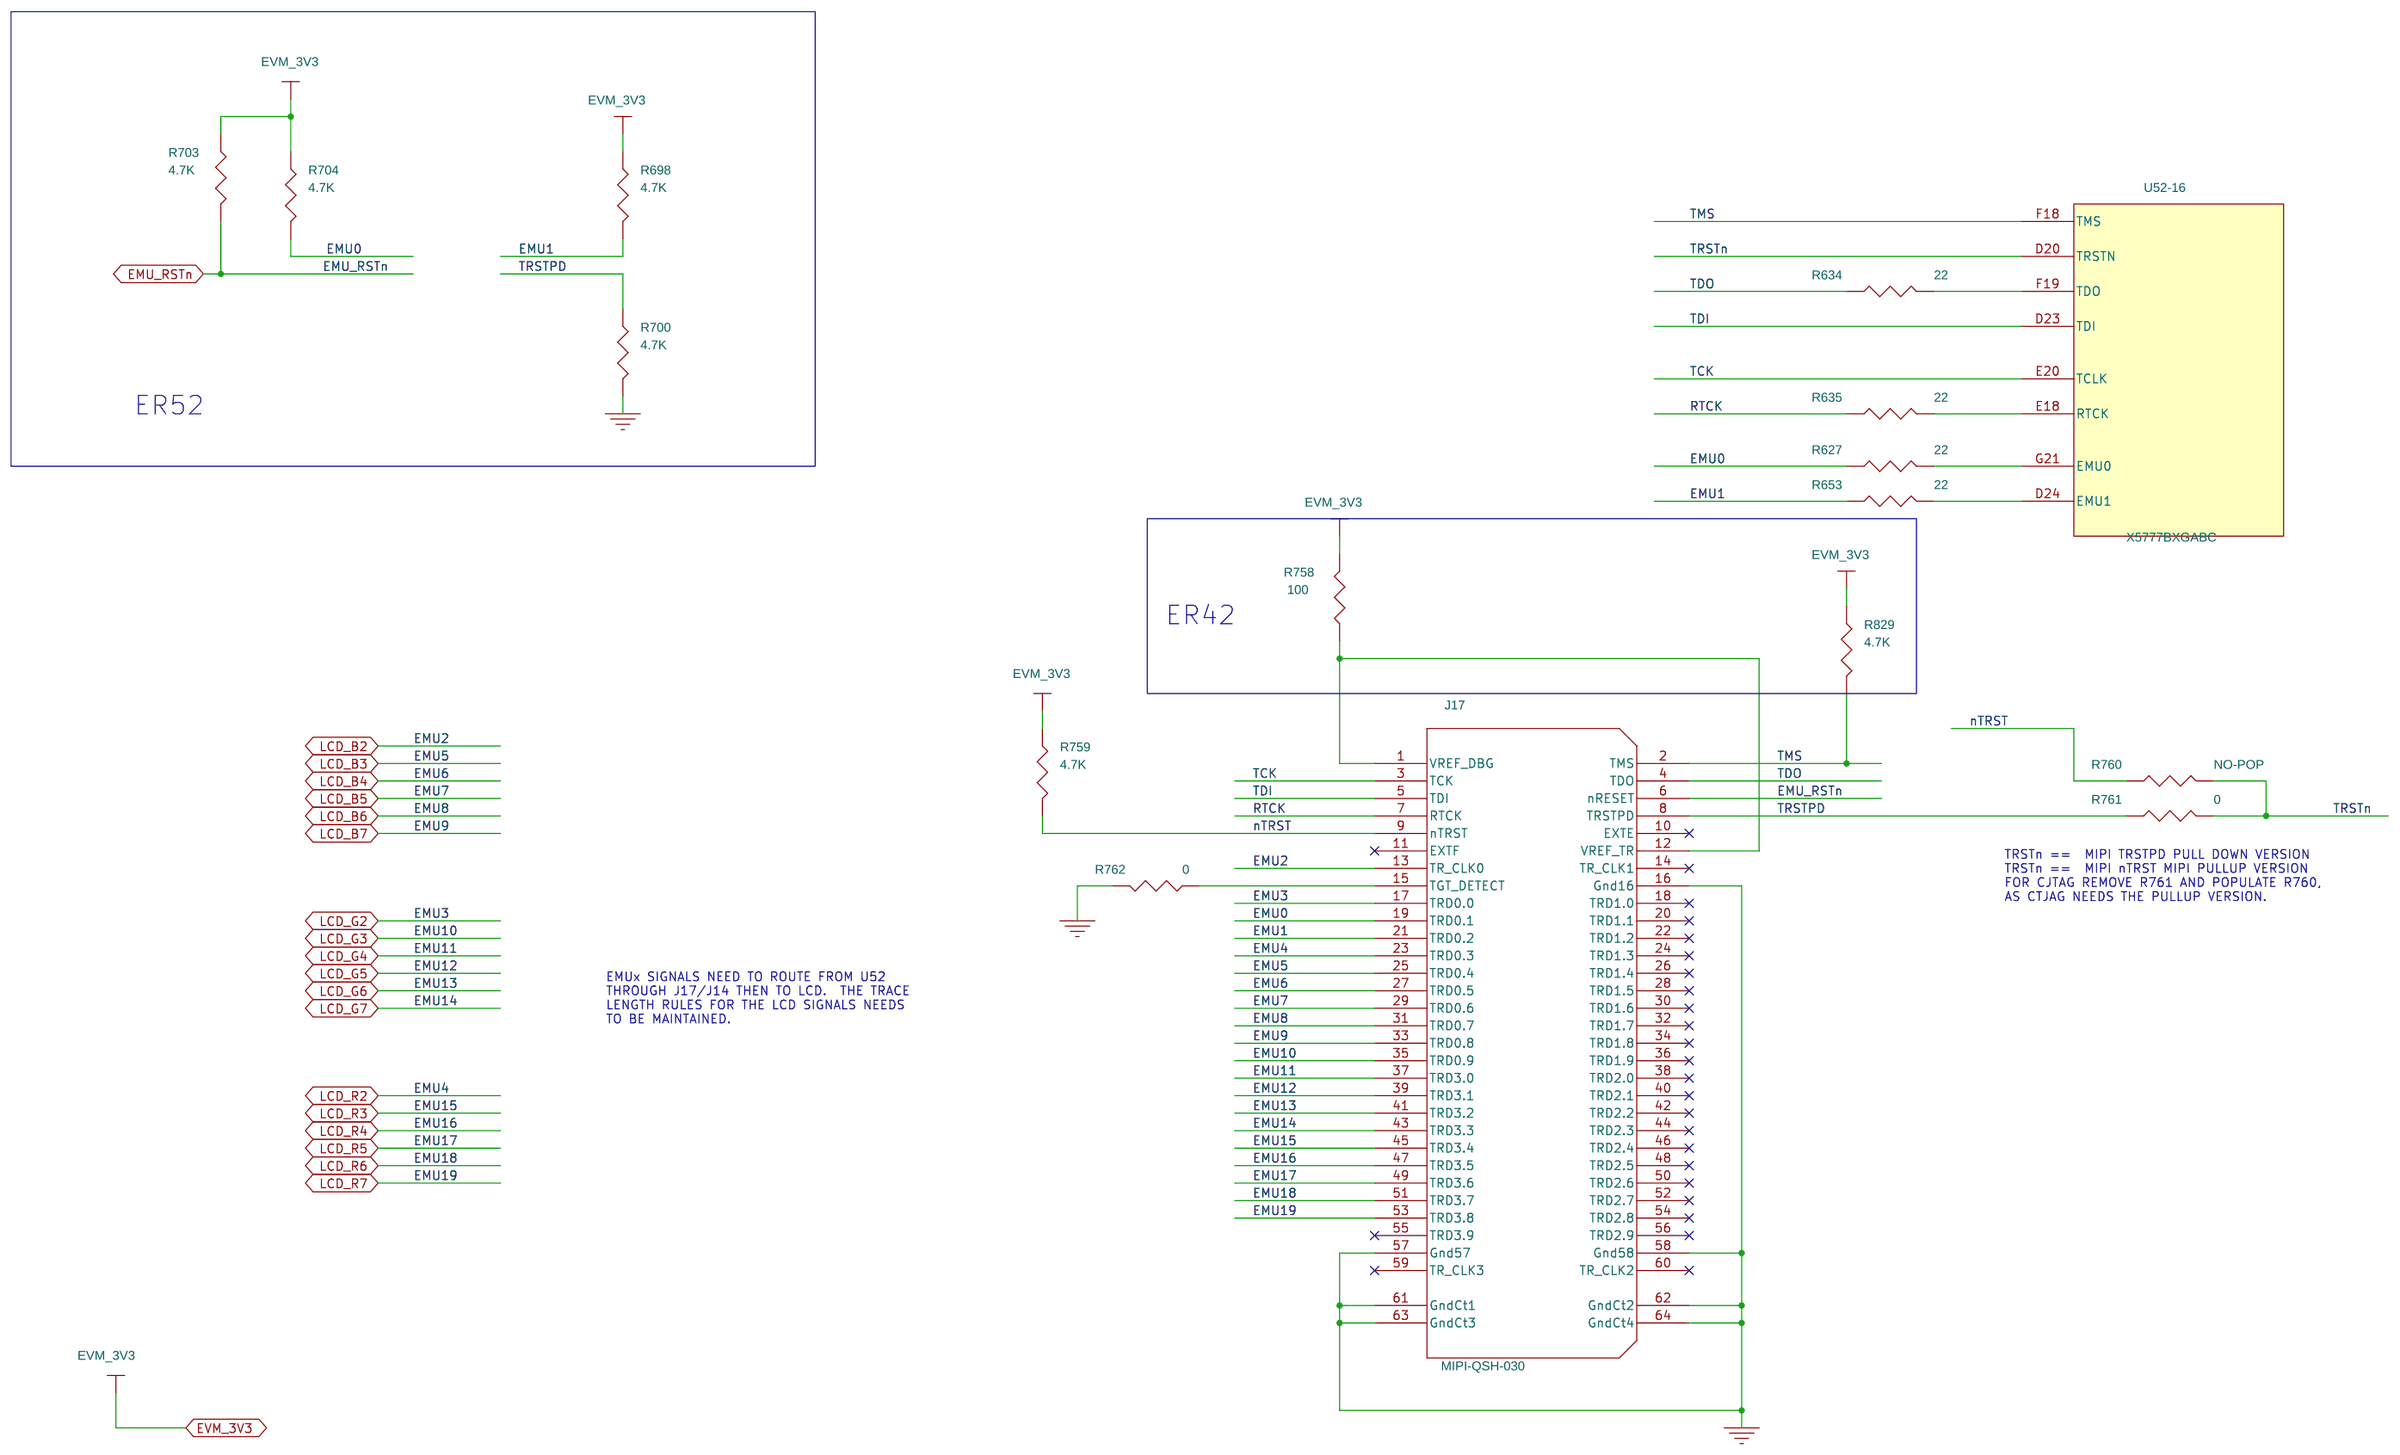
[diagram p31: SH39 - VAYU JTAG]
33 SH40 - VAYU CLOCKS: size B; rev: G2
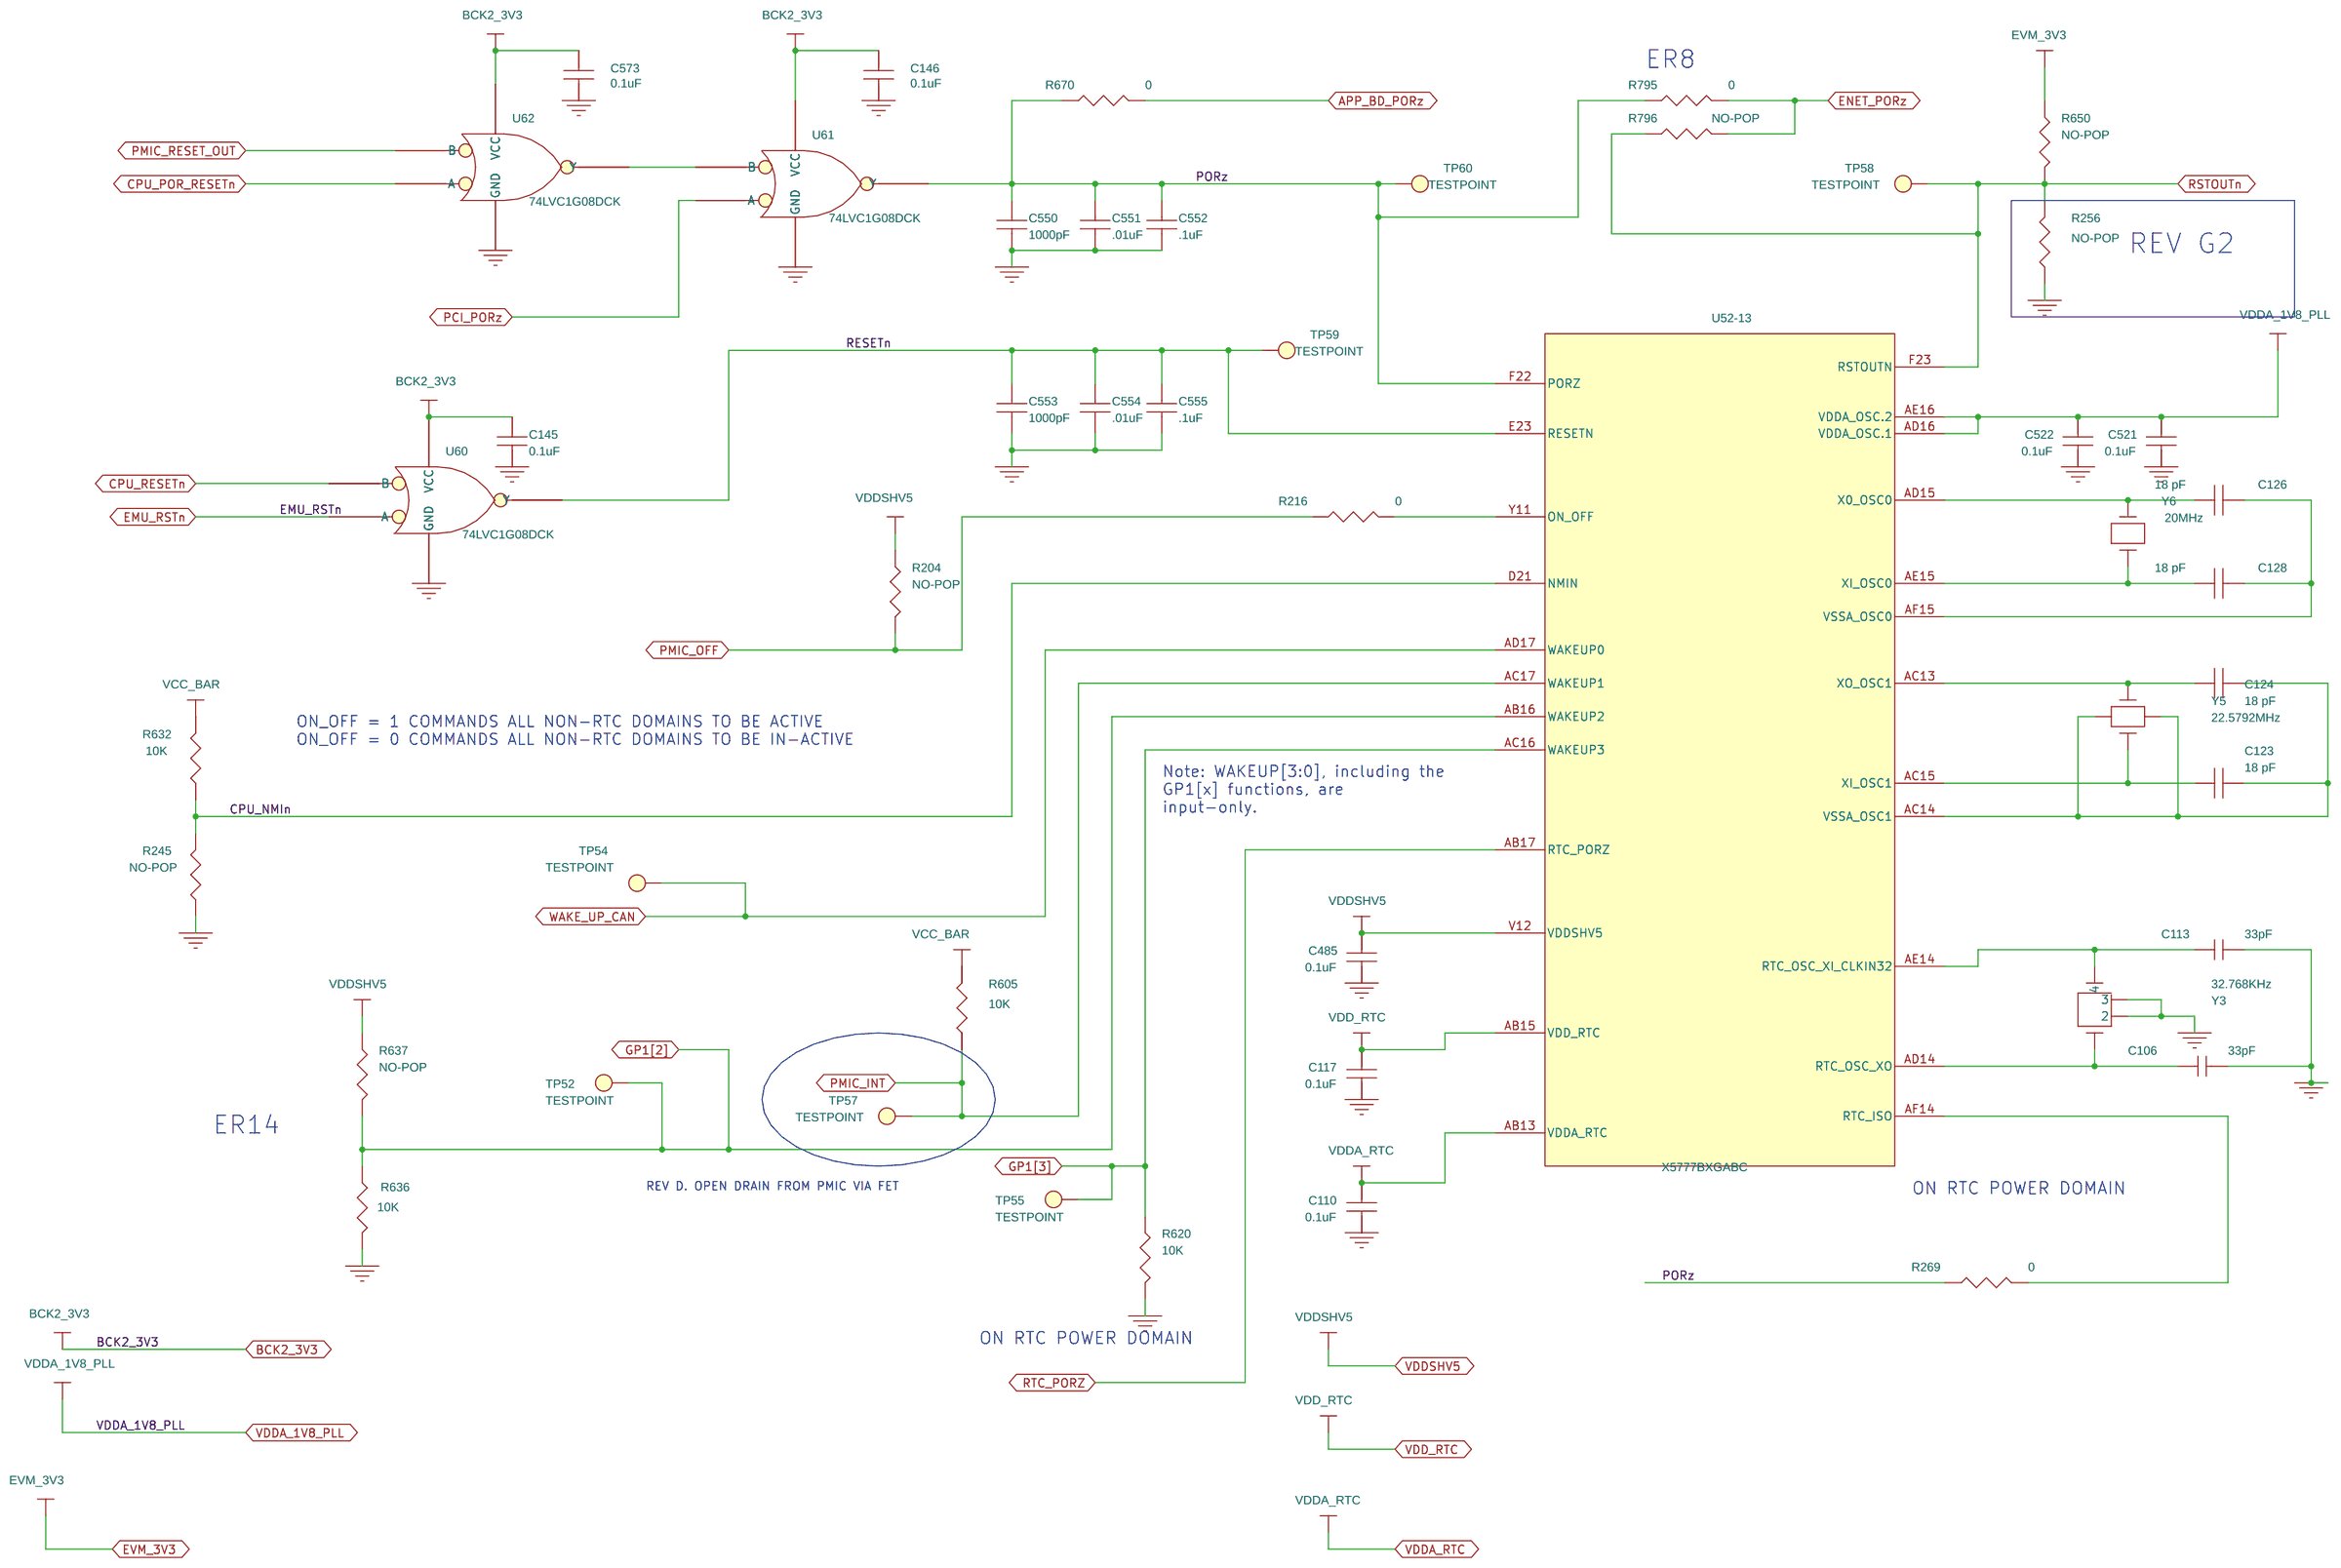
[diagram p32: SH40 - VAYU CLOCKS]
34 SH41 - VAYU INTERNAL LDOS: size B; rev: A
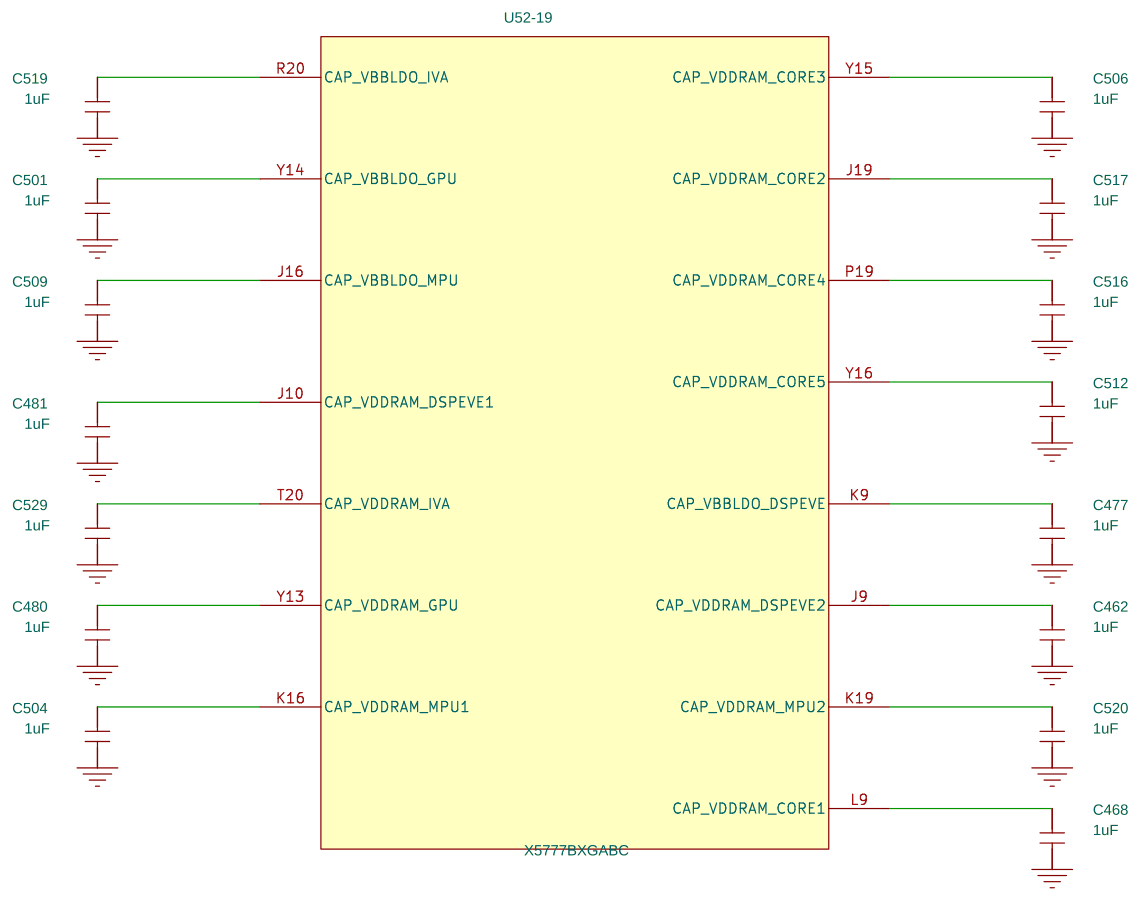
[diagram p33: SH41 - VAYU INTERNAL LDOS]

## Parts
sheet SH28 - VAYU VOUT1 PORT LCD
U52  X5777BXGABC  [sktbga-zkk-6334-p760]  (sections -1,-10,-11,-12,-13,-14,-15,-16,-17,-18,-19,-2,-20,-21,-22,-23,-3,-4,-5,-6,-7,-8,-9)
sheet SH29 - VAYU VIDEO PORTS IN
R173  0  [r201-6p6spc]
R174  0  [r201-6p6spc]
R175  0  [r201-6p6spc]
R176  0  [r201-6p6spc]
R190  0  [r201-6p6spc]
R195  0  [r201-6p6spc]
R543  0  [r201-6p6spc]
R546  0  [r201-6p6spc]
R547  0  [r201-6p6spc]
TP40  TestPoint1_0  [tp1-18rd8]
sheet SH30 - VIN1 MUX
C66  0.1uF  [c402-25]
C83  0.1uF  [c402-25]
C313  .1uF  [c402-25]
C324  0.1uF  [c402-25]
C336  .1uF  [c402-25]
C337  .1uF  [c402-25]
R27  0  [r201-6p6spc]
R29  NO-POP  [r201-6p6spc]
R471  10K  [r201-6p6spc]
R721  0  [r201-6p6spc]
R722  0  [r201-6p6spc]
RU24  SN74CBTLV3257PW  [tssop16-14x70]
RU31  SN74CBTLV16212GR  [dgg56-12x80]
RU40  74CBTLV1G125CRG4  [dck-5]
RU42  74CBTLV1G125CRG4  [dck-5]
RU96  SN74CBTLV16212GR  [dgg56-12x80]
U26  SN74LVC1G04DCK  [dck-5]
sheet SH31 - VIN2 MUX
C82  0.1uF  [c402-25]
C294  0.1uF  [c402-25]
C310  .1uF  [c402-25]
C321  0.1uF  [c402-25]
R466  NO-POP  [r201-6p6spc]
R467  10K  [r201-6p6spc]
R716  0  [r201-6p6spc]
RU19  SN74CBTLV3257PW  [tssop16-14x70]
RU30  SN74CBTLV16212GR  [dgg56-12x80]
RU93  SN74CBT16214DGGR  [dgg56-12x80]
U25  SN74LVC1G04DCK  [dck-5]
sheet SH32 - LCD CONNECTOR
J15  HEADER 50  [molex-54132-50]
R678  10K  [r402-25]
R679  0  [r201-6p6spc]
R680  0  [r201-6p6spc]
R681  0  [r201-6p6spc]
R683  NO-POP  [r402-25]
sheet SH33 - HDMI OUTPUT CONNECTOR
C1  0.1uF  [c402-25]
C3  0.1uF  [c402-25]
C230  0.1uF  [c402-25]
FL5  DLW21SN900HQ2  [EMI-36X15-DLW21-rdpads]
FL6  DLW21SN900HQ2  [EMI-36X15-DLW21-rdpads]
FL7  DLW21SN900HQ2  [EMI-36X15-DLW21-rdpads]
FL8  DLW21SN900HQ2  [EMI-36X15-DLW21-rdpads]
P4  HDMI-RA-19-TYPEA  [hdmi-smt-w-flange-rdpads]
R6  NO-POP  [r402-25]
R7  NO-POP  [r402-25]
R305  NO-POP  [r201-6p6spc]
R321  10K  [r402-25]
R322  10K  [r402-25]
R517  NO-POP  [r201-6p6spc]
R711  NO-POP  [r201-6p6spc]
R712  NO-POP  [r201-6p6spc]
R713  NO-POP  [r201-6p6spc]
U1  TPD12S016RKTR  [rkt24]
U128  tpd1e05u06  [dpy-rdpads]
U129  tpd1e05u06  [dpy-rdpads]
U130  tpd1e05u06  [dpy-rdpads]
U131  tpd1e05u06  [dpy-rdpads]
U132  tpd1e05u06  [dpy-rdpads]
U133  tpd1e05u06  [dpy-rdpads]
U134  tpd1e05u06  [dpy-rdpads]
U135  tpd1e05u06  [dpy-rdpads]
sheet SH34 - FPD LINK
C5  0.1uF  [c402-25]
C6  0.1uF  [c402-25]
C7  4.7uF  [c603-35x45]
C8  4.7uF  [c603-35x45]
C13  4.7uF  [c603-35x45]
C215  0.1uF  [c402-25]
C216  0.1uF  [c402-25]
C228  4.7uF  [c603-35x45]
C229  4.7uF  [c603-35x45]
C231  0.1uF  [c402-25]
C232  0.1uF  [c402-25]
C234  4.7uF  [c603-35x45]
C235  4.7uF  [c603-35x45]
C236  0.1uF  [c402-25]
L2  Ferrite Chip  [l603-35x45]
L3  Ferrite Chip  [l603-35x45]
P1  D4S20D-40ML5  [con_mb261]
R8  10K  [r402-25]
R9  10K  [r402-25]
R10  10K  [r402-25]
R11  10K  [r402-25]
R20  10K  [r402-25]
R22  10K  [r402-25]
R332  10K  [r402-25]
R333  NO-POP  [r402-25]
R338  NO-POP  [r402-25]
U3  DS90UB925QSQE  [QFN48-11X35]
sheet SH35 - CAMERA IF
C704  .1uF  [c402-25]
J5  MOLEX 052559-3679 ( mirror )  [conn36-52559-mirror]
MHC1  MHC1  [mh62]
MHC2  MHC2  [mh62]
R58  22  [r402-25]
R59  22  [r402-25]
R60  22  [r402-25]
R353  22  [r402-25]
R356  22  [r402-25]
R365  10K  [r402-25]
R828  10K  [r402-25]
RN8  RPACK4-22  [rpak8-10x25-28v]
RN9  RPACK4-22  [rpak8-10x25-28v]
RN10  RPACK4-22  [rpak8-10x25-28v]
TP5  TestPoint1  [tp1-6040]
U144  SN74LVC1G125DCKR  [dck-5]
sheet SH36 - SERDES CLOCK
C31  10.0uF  [c603-35x45]
C36  10.0uF  [c603-35x45]
C39  10.0uF  [c603-35x45]
C42  NO-POP  [c402-25]
C254  0.001uF  [c402-25]
C256  0.1uF  [c402-25]
C257  0.01uF  [c402-25]
C261  0.1uF  [c402-25]
C264  0.1uF  [c402-25]
C266  10.0uF  [c603-35x45]
C268  0.1uF  [c402-25]
L4  Ferrite Chip  [l603-35x45]
R62  no-pop  [r402-25]
R63  10K  [r402-25]
R64  10K  [r402-25]
R65  0  [r402-25]
R70  10K  [r402-25]
R71  NO-POP  [r402-25]
R75  0  [r402-25]
TP6  TP  [tp-20RD10]
U9  CDCM9102RHBR  [QFN32_202SQ]
Y2  25.0000MHz  [xtal4-32x35-abm10]
sheet SH38 - PCIe CONNECTORS
C259  .1uF  [c603-35x45]
C262  .1uF  [c603-35x45]
C272  0.1uF  [c402-25]
C275  0.1uF  [c402-25]
C278  .1uF  [c402-25]
C279  0.1uF  [c402-25]
C288  0.1uF  [c402-25]
C291  0.1uF  [c402-25]
C292  0.1uF  [c402-25]
P7  PCI Conn36  [pcie_smt_36]
R76  10K  [r402-25]
R79  100  [r402-25]
R98  1K 1%  [r402-25]
R99  10K  [r402-25]
R104  1K 1%  [r402-25]
R106  1.5K  [r402-25]
R413  10K  [r402-25]
R415  10K  [r402-25]
R416  10K  [r402-25]
R420  10K  [r402-25]
R421  10K  [r402-25]
R434  10K  [r402-25]
R439  NO-POP  [r402-25]
R448  10K  [r402-25]
RU13  74CBTLV1G125CRG4  [dck-5]
U11  74LV1G126CRG4  [dck-5]
U12  TPS3808G09DBVRG4  [DBV6-27X39-6]
U16  TPS3808G09DBVRG4  [DBV6-27X39-6]
U17  SN74LVC1G08DCKRG4  [dck-5]
sheet SH39 - VAYU JTAG
J17  MIPI-QSH-030  [qsh-030-01-f]
R627  22  [r402-25]
R634  22  [r402-25]
R635  22  [r402-25]
R653  22  [r402-25]
R698  4.7K  [r402-25]
R700  4.7K  [r402-25]
R703  4.7K  [r402-25]
R704  4.7K  [r402-25]
R758  100  [r402-25]
R759  4.7K  [r402-25]
R760  NO-POP  [r402-25]
R761  0  [r402-25]
R762  0  [r402-25]
R829  4.7K  [r402-25]
sheet SH40 - VAYU CLOCKS
C106  33pF  [c402-25]
C110  0.1uF  [c201-6p6spc]
C113  33pF  [c402-25]
C117  0.1uF  [c201-6p6spc]
C123  18 pF  [c402-25]
C124  18 pF  [c402-25]
C126  18 pF  [c402-25]
C128  18 pF  [c402-25]
C145  0.1uF  [c402-25]
C146  0.1uF  [c402-25]
C485  0.1uF  [c201-6p6spc]
C521  0.1uF  [c201-6p6spc]
C522  0.1uF  [c201-6p6spc]
C550  1000pF  [c201-6p6spc]
C551  .01uF  [c201-6p6spc]
C552  .1uF  [c201-6p6spc]
C553  1000pF  [c201-6p6spc]
C554  .01uF  [c201-6p6spc]
C555  .1uF  [c201-6p6spc]
C573  0.1uF  [c402-25]
R204  NO-POP  [r201-6p6spc]
R216  0  [r201-6p6spc]
R245  NO-POP  [r201-6p6spc]
R256  NO-POP  [r402-25]
R269  0  [r201-6p6spc]
R605  10K  [r201-6p6spc]
R620  10K  [r201-6p6spc]
R632  10K  [r201-6p6spc]
R636  10K  [r201-6p6spc]
R637  NO-POP  [r201-6p6spc]
R650  NO-POP  [r402-25]
R670  0  [r201-6p6spc]
R795  0  [r402-25]
R796  NO-POP  [r402-25]
TP52  TESTPOINT  [tp-30RD13]
TP54  TESTPOINT  [tp-30RD13]
TP55  TESTPOINT  [tp-30RD13]
TP57  TESTPOINT  [tp-30RD13]
TP58  TESTPOINT  [tp-30RD13]
TP59  TESTPOINT  [tp-30RD13]
TP60  TESTPOINT  [tp-30RD13]
U60  74LVC1G08DCK  [dck-5]
U61  74LVC1G08DCK  [dck-5]
U62  74LVC1G08DCK  [dck-5]
Y3  32.768KHz  [xtal4-23x47-ssp-t7]
Y5  22.5792MHz  [xtal4-55x87]
Y6  20MHz  [xtal2-75x94]
sheet SH41 - VAYU INTERNAL LDOS
C462  1uF  [c402-25]
C468  1uF  [c402-25]
C477  1uF  [c402-25]
C480  1uF  [c402-25]
C481  1uF  [c402-25]
C501  1uF  [c402-25]
C504  1uF  [c402-25]
C506  1uF  [c402-25]
C509  1uF  [c402-25]
C512  1uF  [c402-25]
C516  1uF  [c402-25]
C517  1uF  [c402-25]
C519  1uF  [c402-25]
C520  1uF  [c402-25]
C529  1uF  [c402-25]

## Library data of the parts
U52 = VAYU_DEC_3_2: Part #: 104183-0003R
R27 R173-R176 R190 R195 R216 R269 R543 R546 R547 R670 R679 R716 R721 R722 = R: Part #: 103158-0001R
TP40 = TestPoint1_0: Part #: TP-18RD8-NO-POP
C1 C3 C66 C230 C294 C310 C313 C704 = CAP_NP: Part #: 101587-1100R
C5 C6 C82 C83 C146 C231 C232 C236 C321 C324 C336 C573 = CAP: Part #: 101587-1100R
C275 C278 C279 C288 C292 C337 = CAP_NP_2: Part #: 101587-1100R
R29 R305 = R: Part #: r0201-nopop
R467 R471 R605 R620 R632 R636 = R: Part #: 103158-1003R
RU19 RU24 = SN74CBT3257PW: Part #: 101670-0001R
RU30 RU31 RU96 = SN74CBT16212DGGR: Part #: 102693-0001R
RU13 RU40 RU42 = SN74LVC1G125: Part #: 101689-0125R
U25 U26 = SN74LVC1GU04_1: Part #: 101057-0004R
R204 R245 R466 R517 R637 R711-R713 = R: Part #: R0201-NOPOP
RU93 = SN74CBT16214DGGR_1: Part #: 102513-0001R
J15 = HEADER_50: Part #: 103716-0050R
R8-R11 R20 R22 R63 R64 R70 R99 R321 R322 R332 R365 R415 R416 R421 R434 R448 R678 R828 = R: Part #: 101370-1003R
R680 R681 = R_0: Part #: 103158-0001R
R6 R7 R62 R71 R256 R333 R338 R439 R650 R683 R760 R796 = R: Part #: R0402-NOPOP
FL5-FL8 = DLW21SN900HQ2: Part #: 104184-9000R
P4 = HDMI-RA-19_0: Part #: 103169-0001R
U1 = TPD12S016RKTR_QFN24_3: Part #: 103797-0001R
U128-U135 = tpd1e05u06: Part #: 104410-0001R
C7 C8 C13 C228 C229 C234 C235 = CAP: Part #: 102590-0470R
C215 C216 = CAP_0603: Part #: 101587-1100R
L2-L4 = FERRITE_CHIP_0: Part #: 101858-2201R
P1 = D4S20D-40ML5-Y: Part #: 104234-0001R
U3 = DS90UH925Q_1: Part #: 104304-0001R
J5 = HEADER_36: Part #: 103723-0036R
MHC1 MHC2 = TESTPOINT: Part #: NO-POP
R58 R59 R353 R627 R634 R635 R653 = R: Part #: 101370-2200R
R60 R356 = R_1: Part #: 101370-2200R
RN8-RN10 = R-Pak4_0: Part #: 101327-2200R
TP5 = TestPoint1_0: Part #: 100115-0001R
U144 = SN74LVC1G125: Part #: 101057-0125R
C31 C36 C39 C266 = CAP_NP_0: Part #: 102963-0101R
C42 = CAP_NP_0: Part #: C0402-NOPOP
C254 = CAP_NP_0: Part #: 102058-1102R
C256 C261 C264 C268 = CAP_NP_0: Part #: 101587-1100R
C257 = CAP_NP_0: Part #: 101587-1101R
R65 R75 R761 R762 R795 = R: Part #: 101370-0001R
TP6 = TP_0: Part #: TP-20RD10-NO-POP
U9 = CDCM9102RHBR_2: Part #: 104237-0001R
Y2 = CRYSTAL_4-PIN_0: Part #: 103419-0250R
C259 C262 = CAP_.1_uF_10%_0603: Part #: 100994-1100R
C145 C272 C291 = CAP_NP_1: Part #: 101587-1100R
P7 = PCI_Conn36_1: Part #: 103430-0001R
R76 R413 = RESISTOR: Part #: 101370-1003R
R79 R758 = R: Part #: 101370-1001R
R98 R104 = R_2: Part #: 102145-1002R
R106 = R: Part #: 101370-1502R
R420 = R_2: Part #: 101370-1003R
U11 = SN74LVC1G125_0: Part #: 101057-0126R
U12 U16 = TPS3808G09DBVR_0: Part #: 102020-0009R
U17 U60-U62 = 1G08: Part #: 101057-0008R
J17 = MIPI-QTH-030_1: Part #: 101884-0030R
R698 R700 R703 R704 R759 R829 = R: Part #: 101370-4702R
C106 C113 = Cap_18pF_Cermc_50V_5%_603_0: Part #: 101782-1334R
C110 C117 C485 C521 C522 C552 C555 = CAP: Part #: 103241-1100R
C123 C124 C126 C128 = CAP_NP_3: Part #: 102756-1184R
C550 C553 = CAP: Part #: 103367-1102R
C551 C554 = CAP: Part #: 103241-1101R
TP52 TP54 TP55 TP57-TP60 = TESTPOINT: Part #: TP-30RD13-NO-POP
Y3 = CRYSTAL_0: Part #: 102883-0032R
Y5 = CRYSTAL_22.5792MHz: Part #: 102740-0225R
Y6 = CRYSTAL_0_v2: Part #: 101590-0200R
C462 C468 C477 C480 C481 C501 C504 C506 C509 C512 C516 C517 C519 C520 C529 = CAP_NP: Part #: 102962-0100R

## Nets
3V3_VDDA: C31.1 C254.1 C256.1 C257.1 L4.2 R63.1 R64.1 R70.1 U9.9(VDD3) U9.16(VDD4) U9.18(VDD5) U9.20(VDD6)
GND: C1.2 C3.2 C7.2 C8.2 C13.2 C31.2 C36.2 C39.2 C66.2 C82.2 C83.2 C106.2 C110.2 C113.2 C117.2 C145.2 C146.2 C215.1 C216.2 C228.2 C229.2 C230.2 C231.2 C232.2 C234.2 C235.2 C236.2 C254.2 C256.2 C257.2 C261.2 C264.2 C266.2 C268.2 C272.2 C275.2 C278.2 C279.2 C288.2 C291.2 C292.2 C294.2 C310.2 C313.2 C321.2 C324.2 C336.2 C337.2 C462.2 C468.2 C477.2 C480.2 C481.2 C485.2 C501.2 C504.2 C506.2 C509.2 C512.2 C516.2 C517.2 C519.2 C520.2 C521.2 C522.2 C529.2 C550.2 C551.2 C552.2 C553.2 C554.2 C555.2 C573.2 C704.1 J5.6 J5.8 J5.10 J5.25 J5.26 J15.13 J15.18 J15.27 J15.36 J15.45 J15.50 J17.16(Gnd16) J17.57(Gnd57) J17.58(Gnd58) J17.61(GndCt1) J17.62(GndCt2) J17.63(GndCt3) J17.64(GndCt4) P1.SH1 P1.SH2 P1.SH3 P1.SH4 P4.2(D2_SHIELD) P4.5(D1_SHIELD) P4.8(D0_SHIELD) P4.11(CK_SHIELD) P4.17(GND) P4.MTG1 P4.MTG2 P4.MTG3 P4.MTG4 P7.A4(GND.12) P7.A12(GND.13) P7.A15(GND.14) P7.A18(GND.15) P7.B4(GND.1) P7.B7(GND.2) P7.B13(GND.3) P7.B16(GND.4) P7.B18(GND.5) R9.2 R10.2 R11.2 R62.2 R65.2 R71.2 R75.2 R98.1 R104.1 R245.2 R256.1 R305.2 R333.2 R338.2 R421.2 R448.2 R466.2 R620.2 R636.2 R683.2 R700.2 R716.1 R721.2 R722.2 R762.1 RU13.3(GND) RU19.1(S) RU19.8(GND) RU19.15(~{OE}) RU24.8(GND) RU24.15(~{OE}) RU30.8(GND.1) RU30.19(GND.2) RU30.38(GND.3) RU30.49(GND.4) RU30.55(S2) RU31.8(GND.1) RU31.19(GND.2) RU31.38(GND.3) RU31.49(GND.4) RU31.55(S2) RU40.1(OE) RU40.3(GND) RU42.1(OE) RU42.3(GND) RU93.8(GND.1) RU93.19(GND.2) RU93.38(GND.3) RU93.49(GND.4) RU93.55(S2) RU96.8(GND.1) RU96.19(GND.2) RU96.38(GND.3) RU96.49(GND.4) RU96.55(S2) U1.5(GND1) U1.13(GND2) U1.18(GND3) U3.15(RES0) U3.18(RES1) U3.49(DAP(PWRPAD)) U9.14(GND.1) U9.22(GND.2) U9.33(PWR_PAD) U11.3(GND) U12.2(GND) U16.2(GND) U17.3(GND) U25.3(GND) U26.3(GND) U60.3(GND) U61.3(GND) U62.3(GND) U128.2(GND) U129.2(GND) U130.2(GND) U131.2(GND) U132.2(GND) U133.2(GND) U134.2(GND) U135.2(GND) U144.2(I) U144.3(GND) Y2.2(GND1) Y2.4(GND2) Y3.2 Y3.3 ; also on sheet 3 4 5 7 8 9 10 11 13 15 16 17 18 19 20 21 35 36 37 38 39 40 42 43 46 47 49 50 51 52 53 54 55 56 57 58 60 61 62 63 64 65 66 67 68 69 70 71 72 73 74 75 77 79 80 81 84 85 86 87 88 89
VDD_CDCM9102: C261.1 C264.1 C266.1 C268.1 U9.1(VDD2_OUT1) U9.4(VDD1_OUT0) ; also on sheet 77
VDD_RTC: C117.1 U52.AB15(VDD_RTC) ; also on sheet 76 79
VDDA_1V8_PLL: C521.1 C522.1 U52.AD16(VDDA_OSC.1) U52.AE16(VDDA_OSC.2) ; also on sheet 38 75
VDDA_RTC: C110.1 U52.AB13(VDDA_RTC) ; also on sheet 76
VDDSHV5: C485.1 R204.1 R605.2 R637.1 U52.V12(VDDSHV5) ; also on sheet 3 76 79
VIN2_S0: R466.1 R467.2 RU30.1(S0) RU93.1(S0) U25.2(I) ; also on sheet 9
VIN2_S1: RU30.56(S1) RU93.56(S1) U25.4(O)
VIN[1]A_CLK: RU24.14(4B1) ; also on sheet 61
VIN[1]A_D[0]: RU96.54(1B1) ; also on sheet 61
VIN[1]A_D[1]: RU96.52(2B1) ; also on sheet 61
VIN[1]A_D[2]: RU96.50(3B1) ; also on sheet 61
VIN[1]A_D[3]: RU96.47(4B1) ; also on sheet 61
VIN[1]A_D[4]: RU96.45(5B1) ; also on sheet 61
VIN[1]A_D[5]: RU96.43(6B1) ; also on sheet 61
VIN[1]A_D[6]: RU96.41(7B1) ; also on sheet 61
VIN[1]A_D[7]: RU96.39(8B1) ; also on sheet 61
VIN[1]A_D[8]: RU96.36(9B1) ; also on sheet 61
VIN[1]A_D[9]: RU96.34(10B1) ; also on sheet 61
VIN[1]A_D[10]: RU96.32(11B1) ; also on sheet 61
VIN[1]A_D[11]: RU96.30(12B1) ; also on sheet 61
VIN[1]A_D[12]: RU31.54(1B1) ; also on sheet 61
VIN[1]A_D[13]: RU31.52(2B1) ; also on sheet 61
VIN[1]A_D[14]: RU31.50(3B1) ; also on sheet 61
VIN[1]A_D[15]: RU31.47(4B1) ; also on sheet 61
VIN[1]A_D[16]: RU31.45(5B1) ; also on sheet 61
VIN[1]A_D[17]: RU31.43(6B1) ; also on sheet 61
VIN[1]A_D[18]: RU31.41(7B1) ; also on sheet 61
VIN[1]A_D[19]: RU31.39(8B1) ; also on sheet 61
VIN[1]A_D[20]: RU31.36(9B1) ; also on sheet 61
VIN[1]A_D[21]: RU31.34(10B1) ; also on sheet 61
VIN[1]A_D[22]: RU31.32(11B1) ; also on sheet 61
VIN[1]A_D[23]: RU31.30(12B1) ; also on sheet 61
VIN[1]A_DE0: RU24.2(1B1) ; also on sheet 61
VIN[1]A_FLD0: RU40.4(O) ; also on sheet 61
VIN[1]A_HSYNC0: RU24.5(2B1) ; also on sheet 61
VIN[1]A_VSYNC0: RU24.11(3B1) ; also on sheet 61
VIN[1]B_CLK1: RU42.4(O) ; also on sheet 61
VIN[2]A_CLK: RU19.2(1B1) ; also on sheet 61
VIN[2]A_D[0]: RU30.53(1B2) ; also on sheet 61
VIN[2]A_D[1]: RU30.51(2B2) ; also on sheet 61
VIN[2]A_D[2]: RU30.48(3B2) ; also on sheet 61
VIN[2]A_D[3]: RU30.46(4B2) ; also on sheet 61
VIN[2]A_D[4]: RU30.44(5B2) ; also on sheet 61
VIN[2]A_D[5]: RU30.42(6B2) ; also on sheet 61
VIN[2]A_D[6]: RU30.40(7B2) ; also on sheet 61
VIN[2]A_D[7]: RU30.37(8B2) ; also on sheet 61
VIN[2]A_D[8]: RU30.35(9B2) ; also on sheet 61
VIN[2]A_D[9]: RU30.33(10B2) ; also on sheet 61
VIN[2]A_D[10]: RU30.31(11B2) ; also on sheet 61
VIN[2]A_D[11]: RU30.29(12B2) ; also on sheet 61
VIN[2]A_D[12]: RU93.53(1B2) ; also on sheet 61
VIN[2]A_D[13]: RU93.51(2B2) ; also on sheet 61
VIN[2]A_D[14]: RU93.48(3B2) ; also on sheet 61
VIN[2]A_D[15]: RU93.46(4B2) ; also on sheet 61
VIN[2]A_D[16]: RU93.44(5B2) ; also on sheet 61
VIN[2]A_D[17]: RU93.42(6B2) ; also on sheet 61
VIN[2]A_D[18]: RU93.40(7B2) ; also on sheet 61
VIN[2]A_D[19]: RU93.37(8B2) ; also on sheet 61
VIN[2]A_D[20]: RU93.35(9B2) ; also on sheet 61
VIN[2]A_D[21]: RU93.33(10B2) ; also on sheet 61
VIN[2]A_D[22]: RU93.31(11B2) ; also on sheet 61
VIN[2]A_D[23]: RU93.29(12B2) ; also on sheet 61
VIN[2]A_DE0: RU19.5(2B1) ; also on sheet 61
VIN[2]A_HSYNC: RU19.11(3B1) ; also on sheet 61
VIN[2]A_VSYNC: RU19.14(4B1) ; also on sheet 61
APP_BD_PORz: R670.2 ; also on sheet 61
BCK2_3V3: C145.1 C146.1 C573.1 U60.5(VCC) U61.5(VCC) U62.5(VCC) ; also on sheet 77
C_SPI1_CS2n: U1.3(HPD_A) ; also on sheet 87
C_SPI1_CS3n: U1.24(CEC_A) ; also on sheet 87
C_VIN[1]A_CLK: R195.1 RU24.12(4A)
C_VIN[1]A_D[0]: RU96.2(1A1) U52.AE8(VIN1A_D0)
C_VIN[1]A_D[1]: RU96.4(2A1) U52.AD8(VIN1A_D1)
C_VIN[1]A_D[2]: RU96.6(3A1) U52.AG7(VIN1A_D2)
C_VIN[1]A_D[3]: RU96.9(4A1) U52.AH6(VIN1A_D3)
C_VIN[1]A_D[4]: RU96.11(5A1) U52.AH3(VIN1A_D4)
C_VIN[1]A_D[5]: RU96.13(6A1) U52.AH5(VIN1A_D5)
C_VIN[1]A_D[6]: RU96.15(7A1) U52.AG6(VIN1A_D6)
C_VIN[1]A_D[7]: RU96.18(8A1) U52.AH4(VIN1A_D7)
C_VIN[1]A_D[8]: RU96.21(9A1) U52.AG4(VIN1A_D8)
C_VIN[1]A_D[9]: RU96.23(10A1) U52.AG2(VIN1A_D9)
C_VIN[1]A_D[10]: RU96.25(11A1) U52.AG3(VIN1A_D10)
C_VIN[1]A_D[11]: RU96.27(12A1) U52.AG5(VIN1A_D11)
C_VIN[1]A_D[12]: RU31.2(1A1) U52.AF2(VIN1A_D12)
C_VIN[1]A_D[13]: RU31.4(2A1) U52.AF6(VIN1A_D13)
C_VIN[1]A_D[14]: RU31.6(3A1) U52.AF3(VIN1A_D14)
C_VIN[1]A_D[15]: RU31.9(4A1) U52.AF4(VIN1A_D15)
C_VIN[1]A_D[16]: RU31.11(5A1) U52.AF1(VIN1A_D16)
C_VIN[1]A_D[17]: RU31.13(6A1) U52.AE3(VIN1A_D17)
C_VIN[1]A_D[18]: RU31.15(7A1) U52.AE5(VIN1A_D18)
C_VIN[1]A_D[19]: RU31.18(8A1) U52.AE1(VIN1A_D19)
C_VIN[1]A_D[20]: RU31.21(9A1) U52.AE2(VIN1A_D20)
C_VIN[1]A_D[21]: RU31.23(10A1) U52.AE6(VIN1A_D21)
C_VIN[1]A_D[22]: RU31.25(11A1) U52.AD2(VIN1A_D22)
C_VIN[1]A_D[23]: RU31.27(12A1) U52.AD3(VIN1A_D23)
C_VIN[1]A_DE0: RU24.4(1A) U52.AD9(VIN1A_DE0)
C_VIN[1]A_FLD0: RU40.2(I) U52.AF9(VIN1A_FLD0)
C_VIN[1]A_HSYNC0: RU24.7(2A) U52.AE9(VIN1A_HSYNC0)
C_VIN[1]A_VSYNC0: RU24.9(3A) U52.AF8(VIN1A_VSYNC0)
C_VIN[1]B_CLK1: R190.1 RU42.2(I)
C_VIN[2]A_CLK: R173.1 RU19.4(1A)
C_VIN[2]A_D[0]: RU30.2(1A1) U52.F2(VIN2A_D0)
C_VIN[2]A_D[1]: RU30.4(2A1) U52.F3(VIN2A_D1)
C_VIN[2]A_D[2]: RU30.6(3A1) U52.D1(VIN2A_D2)
C_VIN[2]A_D[3]: RU30.9(4A1) U52.E2(VIN2A_D3)
C_VIN[2]A_D[4]: RU30.11(5A1) U52.D2(VIN2A_D4)
C_VIN[2]A_D[5]: RU30.13(6A1) U52.F4(VIN2A_D5)
C_VIN[2]A_D[6]: RU30.15(7A1) U52.C1(VIN2A_D6)
C_VIN[2]A_D[7]: RU30.18(8A1) U52.E4(VIN2A_D7)
C_VIN[2]A_D[8]: RU30.21(9A1) U52.F5(VIN2A_D8)
C_VIN[2]A_D[9]: RU30.23(10A1) U52.E6(VIN2A_D9)
C_VIN[2]A_D[10]: RU30.25(11A1) U52.D3(VIN2A_D10)
C_VIN[2]A_D[11]: RU30.27(12A1) U52.F6(VIN2A_D11)
C_VIN[2]A_D[12]: R547.1 RU93.2(1A)
C_VIN[2]A_D[13]: R174.1 RU93.4(2A)
C_VIN[2]A_D[14]: R176.1 RU93.6(3A)
C_VIN[2]A_D[15]: R543.1 RU93.9(4A)
C_VIN[2]A_D[16]: R175.1 RU93.11(5A)
C_VIN[2]A_D[17]: R546.1 RU93.13(6A)
C_VIN[2]A_D[18]: RU93.15(7A) U52.C5(VIN2A_D18)
C_VIN[2]A_D[19]: RU93.18(8A) U52.A3(VIN2A_D19)
C_VIN[2]A_D[20]: RU93.21(9A) U52.B3(VIN2A_D20)
C_VIN[2]A_D[21]: RU93.23(10A) U52.B4(VIN2A_D21)
C_VIN[2]A_D[22]: RU93.25(11A) U52.B5(VIN2A_D22)
C_VIN[2]A_D[23]: RU93.27(12A) U52.A4(VIN2A_D23)
C_VIN[2]A_DE0: RU19.7(2A) U52.G2(VIN2A_DE0)
C_VIN[2]A_HSYNC0: RU19.9(3A) U52.G1(VIN2A_HSYNC0)
C_VIN[2]A_VSYNC0: RU19.12(4A) U52.G6(VIN2A_VSYNC0)
CAM_DE0: R29.1 RU24.3(1B2)
CAM_FPD_MUX_S0: R471.2 RU31.1(S0) RU96.1(S0) U26.2(I) ; also on sheet 9
CAM_FPD_MUX_S1: RU24.1(S) RU31.56(S1) RU96.56(S1) U26.4(O)
CAM_SPI[1]_CS[0]n: J5.34 R365.1 ; also on sheet 87
CAM_SPI[1]_MISO: J5.31 ; also on sheet 87
CAM_SPI[1]_MOSI: J5.36 ; also on sheet 87
CAM_SPI[1]_SCLK: J5.32 ; also on sheet 87
CAMERA_CLK: R58.1 RU24.13(4B2)
CAMERA_D0: R356.1 RU96.53(1B2)
CAMERA_D1: R60.1 RU96.51(2B2)
CAMERA_D2: RN8.5(R4B) RU96.48(3B2)
CAMERA_D3: RN8.6(R3B) RU96.46(4B2)
CAMERA_D4: RN8.7(R2B) RU96.44(5B2)
CAMERA_D5: RN8.8(R1B) RU96.42(6B2)
CAMERA_D6: RN9.5(R4B) RU96.40(7B2)
CAMERA_D7: RN9.6(R3B) RU96.37(8B2)
CAMERA_D8: RN9.7(R2B) RU96.35(9B2)
CAMERA_D9: RN9.8(R1B) RU96.33(10B2)
CAMERA_D10: RN10.5(R4B) RU96.31(11B2)
CAMERA_D11: RN10.6(R3B) RU96.29(12B2)
CAMERA_D12: RN10.7(R2B) RU31.53(1B2)
CAMERA_D13: RN10.8(R1B) RU31.51(2B2)
CAMERA_HSYNC: R27.2 R29.2 R353.1
CAMERA_VSYNC: R59.1 RU24.10(3B2)
CON.PCIE_RXN0: P7.A17(PERn0) ; also on sheet 89
CON.PCIE_RXP0: P7.A16(PERp0) ; also on sheet 89
CON.PCIE_TXN0: P7.B15(PETn0) ; also on sheet 89
CON.PCIE_TXP0: P7.B14(PETp0) ; also on sheet 89
CON_LCD_GP0[31]: J15.15 R679.2
CON_LCD_I2C_SCL: J15.17 R681.2
CON_LCD_I2C_SDA: J15.16 R680.2
CON_LCD_PWR_DN: J15.14 R678.2 R683.1 ; also on sheet 9
CPU_HDMI_TX0+: FL7.1 ; also on sheet 21
CPU_HDMI_TX0-: FL7.4 ; also on sheet 21
CPU_HDMI_TX1+: FL6.1 ; also on sheet 21
CPU_HDMI_TX1-: FL6.4 ; also on sheet 21
CPU_HDMI_TX2+: FL5.1 ; also on sheet 21
CPU_HDMI_TX2-: FL5.4 ; also on sheet 21
CPU_HDMI_TXC+: FL8.1 ; also on sheet 21
CPU_HDMI_TXC-: FL8.4 ; also on sheet 21
CPU_NMIn: R245.1 R632.2 U52.D21(NMIN)
CPU_POR_RESETn: U62.2(A) ; also on sheet 79
CPU_RESETn: U60.1(B) ; also on sheet 79
EMAC[1]_RXC: RU93.41(7B1) ; also on sheet 57
EMAC[1]_RXCTL: RU93.39(8B1) ; also on sheet 57
EMAC[1]_RXD0: RU93.30(12B1) ; also on sheet 57
EMAC[1]_RXD1: RU93.32(11B1) ; also on sheet 57
EMAC[1]_RXD2: RU93.34(10B1) ; also on sheet 57
EMAC[1]_RXD3: RU93.36(9B1) ; also on sheet 57
EMAC[1]_TXC: RU93.54(1B1) ; also on sheet 57
EMAC[1]_TXCTL: RU93.52(2B1) ; also on sheet 57
EMAC[1]_TXD0: RU93.43(6B1) ; also on sheet 57
EMAC[1]_TXD1: RU93.45(5B1) ; also on sheet 57
EMAC[1]_TXD2: RU93.47(4B1) ; also on sheet 57
EMAC[1]_TXD3: RU93.50(3B1) ; also on sheet 57
EMU0: J17.19(TRD0.1) R627.1 R704.2
EMU1: J17.21(TRD0.2) R653.1 R698.2
EMU_RSTn: J17.6(nRESET) R703.2 U60.2(A)
ENET_PORz: R795.2 R796.2 ; also on sheet 56 57
EVM_1V8: J15.7 J15.8 ; also on sheet 8 10 52 53 61 69 74
EVM_3V3: C1.1 C66.1 C82.1 C83.1 C272.1 C278.1 C291.1 C294.1 C310.1 C313.1 C324.1 C336.1 C337.1 C704.2 J5.1 J5.2 J5.3 J15.4 J15.5 J15.6 L2.2 L3.1 L4.1 R6.2 R7.2 R8.1 R20.1 R22.1 R76.2 R106.1 R321.1 R322.1 R332.1 R365.2 R413.2 R415.1 R416.1 R420.2 R434.1 R467.1 R471.1 R517.2 R632.1 R650.1 R678.1 R698.1 R703.1 R704.1 R758.1 R759.1 R828.2 R829.1 RU13.5(VCC) RU19.16(VCC) RU24.16(VCC) RU30.17(VCC.1) RU31.17(VCC.1) RU40.5(VCC) RU42.5(VCC) RU96.17(VCC.1) U1.23(VCCA) U11.5(VCC) U17.5(VCC) U25.5(VCC) U26.5(VCC) U144.5(VCC) ; also on sheet 3 4 5 7 8 9 10 11 14 15 16 17 18 49 50 51 52 53 56 57 58 60 61 69 70 78 84 85 86 87 88
EVM_5V0: C230.1 C275.1 C288.1 J5.4 J5.5 J15.1 J15.2 J15.3 R711.2 R712.2 R713.1 U1.10(VCC5V) U12.6(VDD) U16.6(VDD) ; also on sheet 3 49 54 61 78
EVM_12V: P7.A2(+12V.4) P7.A3(+12V.5) P7.B1(+12V.1) P7.B2(+12V.2) P7.B3(+12V.3) R99.1 ; also on sheet 11 61 67 80
FPD_DOUT+: C5.2 P1.3
FPD_DOUT-: C6.2 P1.1
GP1[2]: R636.1 R637.2 R679.1 TP52.1(TP) U52.AB16(WAKEUP2) ; also on sheet 60
GP1[3]: R620.1 TP55.1(TP) U52.AC16(WAKEUP3) ; also on sheet 60
HDMI_CEC_B: P4.13(CE_REMOTE) R517.1 U1.6(CEC_B)
HDMI_CT_HPD: R322.2 U1.11(CT_HPD) ; also on sheet 9
HDMI_DSCL: R7.1 U1.1(SCL_A) ; also on sheet 84
HDMI_DSDA: R6.1 U1.2(SDA_A) ; also on sheet 84
HDMI_HPD_B: P4.19(HP_DET) R305.1 R713.2 U1.9(HPD_B)
HDMI_LS_OE: R321.2 U1.4(LS_OE) ; also on sheet 9
HDMI_SCL_B: P4.15(DDC_CLK) R711.1 U1.7(SCL_B)
HDMI_SDA_B: P4.16(DDC_DATA) R712.1 U1.8(SDA_B)
HDMI_TX0+: FL7.2 P4.7(D0+) U132.1(IO)
HDMI_TX0-: FL7.3 P4.9(D0-) U133.1(IO)
HDMI_TX1+: FL6.2 P4.4(D1+) U130.1(IO)
HDMI_TX1-: FL6.3 P4.6(D1-) U131.1(IO)
HDMI_TX2+: FL5.2 P4.1(D2+) U128.1(IO)
HDMI_TX2-: FL5.3 P4.3(D2-) U129.1(IO)
HDMI_TXC+: FL8.2 P4.10(CK+) U134.1(IO)
HDMI_TXC-: FL8.3 P4.12(CK-) U135.1(IO)
I2C1_SCL: R681.1 ; also on sheet 9 11 53 55 61 87 88
I2C1_SDA: R680.1 ; also on sheet 9 11 53 55 61 87 88
I2C2_SCL: J5.29 U3.8(SCL) ; also on sheet 9 62 84
I2C2_SDA: J5.30 U3.9(SDA) ; also on sheet 9 62 84
LCD_B0: J15.37 ; also on sheet 22
LCD_B1: J15.38 ; also on sheet 22
LCD_B2: J15.39 J17.13(TR_CLK0) ; also on sheet 22
LCD_B3: J15.40 J17.25(TRD0.4) ; also on sheet 22
LCD_B4: J15.41 J17.27(TRD0.5) ; also on sheet 22
LCD_B5: J15.42 J17.29(TRD0.6) ; also on sheet 22
LCD_B6: J15.43 J17.31(TRD0.7) ; also on sheet 22
LCD_B7: J15.44 J17.33(TRD0.8) ; also on sheet 22
LCD_DE: J15.46 ; also on sheet 22
LCD_G0: J15.28 ; also on sheet 22
LCD_G1: J15.29 ; also on sheet 22
LCD_G2: J15.30 J17.17(TRD0.0) ; also on sheet 22
LCD_G3: J15.31 J17.35(TRD0.9) ; also on sheet 22
LCD_G4: J15.32 J17.37(TRD3.0) ; also on sheet 22
LCD_G5: J15.33 J17.39(TRD3.1) ; also on sheet 22
LCD_G6: J15.34 J17.41(TRD3.2) ; also on sheet 22
LCD_G7: J15.35 J17.43(TRD3.3) ; also on sheet 22
LCD_HS: J15.47 ; also on sheet 22
LCD_PCLK: J15.49 ; also on sheet 22
LCD_R0: J15.19 ; also on sheet 22
LCD_R1: J15.20 ; also on sheet 22
LCD_R2: J15.21 J17.23(TRD0.3) ; also on sheet 22
LCD_R3: J15.22 J17.45(TRD3.4) ; also on sheet 22
LCD_R4: J15.23 J17.47(TRD3.5) ; also on sheet 22
LCD_R5: J15.24 J17.49(TRD3.6) ; also on sheet 22
LCD_R6: J15.25 J17.51(TRD3.7) ; also on sheet 22
LCD_R7: J15.26 J17.53(TRD3.8) ; also on sheet 22
LCD_VS: J15.48 ; also on sheet 22
nTRST: J17.9(nTRST) R759.2 R760.1
PCI_CONN_REFN: C262.1 U9.5(OUT0N)
PCI_CONN_REFP: C259.1 U9.6(OUT0P)
PCI_PORz: R76.1 U11.4(O) U61.2(A)
PCI_RESET_SEL: RU13.1(OE) U11.1(OE) ; also on sheet 18
PCI_SW_RESETn: R434.2 U17.1(B) ; also on sheet 9
PMIC_INT: R605.1 TP57.1(TP) U52.AC17(WAKEUP1) ; also on sheet 63
PMIC_OFF: R204.2 R216.1 ; also on sheet 3 63
PMIC_RESET_OUT: U62.1(B) ; also on sheet 63
PORz: C550.1 C551.1 C552.1 R269.2 R670.1 R795.1 TP60.1(TP) U52.F22(PORZ) U61.4(Y)
PS_EVM_3V3: P7.A9(+3.3V.2) P7.A10(+3.3V.3) P7.B8(+3.3V.1) ; also on sheet 63 64 65 66 67 68 69 70 71 72 73 74 75 77 79
PWR_CBT: C321.1 RU93.17(VCC.1) ; also on sheet 78
R_CAMERA_HSYNC: R27.1 RU24.6(2B2)
RC_VIN[1]A_CLK: R195.2 U52.AG8(VIN1A_CLK0)
RC_VIN[1]B_CLK1: R190.2 U52.AH7(VIN1B_CLK1)
RC_VIN[2]A_CLK: R173.2 U52.E1(VIN2A_CLK0)
RC_VIN[2]A_D[12]: R547.2 U52.D5(VIN2A_D12)
RC_VIN[2]A_D[13]: R174.2 U52.C2(VIN2A_D13)
RC_VIN[2]A_D[14]: R176.2 U52.C3(VIN2A_D14)
RC_VIN[2]A_D[15]: R543.2 U52.C4(VIN2A_D15)
RC_VIN[2]A_D[16]: R175.2 U52.B2(VIN2A_D16)
RC_VIN[2]A_D[17]: R546.2 U52.D6(VIN2A_D17)
REFCLKn: C262.2 P7.A14(REFCLK-) R79.1
REFCLKp: C259.2 P7.A13(REFCLK+) R79.2
RESETn: C553.1 C554.1 C555.1 TP59.1(TP) U52.E23(RESETN) U60.4(Y)
RSTOUTn: R256.2 R650.2 R796.1 TP58.1(TP) U9.12(RSTn) U52.F23(RSTOUTN) U144.1(OE) ; also on sheet 4 7 8 11 51 55 63
RTC_PORZ: U52.AB17(RTC_PORZ) ; also on sheet 79
RTCK: J17.7(RTCK) R635.1
SERDES_IN_REFN: U9.2(OUT1N) ; also on sheet 89
SERDES_IN_REFP: U9.3(OUT1P) ; also on sheet 89
TCK: J17.3(TCK) U52.E20(TCLK)
TDI: J17.5(TDI) U52.D23(TDI)
TDO: J17.4(TDO) R634.1
TMS: J17.2(TMS) R829.2 U52.F18(TMS)
TRSTn: R760.2 R761.2 U52.D20(TRSTN)
TRSTPD: J17.8(TRSTPD) R700.1 R761.1
TS_LCD_GPIO1: J15.9 ; also on sheet 9
TS_LCD_GPIO2: J15.10 ; also on sheet 9
TS_LCD_GPIO3: J15.11 ; also on sheet 9
TS_LCD_GPIO4: J15.12 ; also on sheet 9
VOUT3B_CLK: U3.10(PCLK) ; also on sheet 16
VOUT3B_D0: U3.43(B0/O4) ; also on sheet 15
VOUT3B_D1: U3.44(B1/I2S_DB/O5) ; also on sheet 15
VOUT3B_D2: U3.45(B2) ; also on sheet 15
VOUT3B_D3: U3.46(B3) ; also on sheet 15
VOUT3B_D4: U3.47(B4) ; also on sheet 15
VOUT3B_D5: U3.48(B5) ; also on sheet 15
VOUT3B_D6: U3.1(B6) ; also on sheet 15
VOUT3B_D7: U3.2(B7) ; also on sheet 15
VOUT3B_D8: U3.35(G0/IO2) ; also on sheet 15
VOUT3B_D9: U3.36(G1/IO3) ; also on sheet 15
VOUT3B_D10: U3.37(G2) ; also on sheet 15
VOUT3B_D11: U3.38(G3) ; also on sheet 15
VOUT3B_D12: U3.39(G4) ; also on sheet 15
VOUT3B_D13: U3.40(G5) ; also on sheet 15
VOUT3B_D14: U3.41(G6) ; also on sheet 15
VOUT3B_D15: U3.42(G7) ; also on sheet 15
VOUT3B_D16: U3.25(R0/IO0) ; also on sheet 15
VOUT3B_D17: U3.26(R1/IO1) ; also on sheet 15
VOUT3B_D18: U3.27(R2) ; also on sheet 15
VOUT3B_D19: U3.28(R3) ; also on sheet 15
VOUT3B_D20: U3.29(R4) ; also on sheet 15
VOUT3B_D21: U3.32(R5) ; also on sheet 15
VOUT3B_D22: U3.33(R6) ; also on sheet 15
VOUT3B_D23: U3.34(R7) ; also on sheet 15
VOUT3B_DE: U3.5(DE) ; also on sheet 16
VOUT3B_HSYNC: U3.3(HS) ; also on sheet 16
VOUT3B_INTB: R22.2 U3.31(INTB) ; also on sheet 16
VOUT3B_VSYNC: U3.4(VS) ; also on sheet 16
WAKE_UP_CAN: TP54.1(TP) U52.AD17(WAKEUP0) ; also on sheet 87
N17034340: R216.2 U52.Y11(ON_OFF)
N17473174: C215.2 P1.2
N17473178: C216.1 P1.4
N18147585: R716.2 RU30.3(1A2) RU30.5(2A2) RU30.7(3A2) RU30.10(4A2) RU30.12(5A2) RU30.14(6A2) RU30.16(7A2) RU30.20(8A2) RU30.22(9A2) RU30.24(10A2) RU30.26(11A2) RU30.28(12A2)
N18149573: R721.1 RU96.3(1A2) RU96.5(2A2) RU96.7(3A2) RU96.10(4A2) RU96.12(5A2) RU96.14(6A2) RU96.16(7A2) RU96.20(8A2) RU96.22(9A2) RU96.24(10A2) RU96.26(11A2) RU96.28(12A2)
N18149929: R722.1 RU31.3(1A2) RU31.5(2A2) RU31.7(3A2) RU31.10(4A2) RU31.12(5A2) RU31.14(6A2) RU31.16(7A2) RU31.20(8A2) RU31.22(9A2) RU31.24(10A2) RU31.26(11A2) RU31.28(12A2)
N18657599: R635.2 U52.E18(RTCK)
N18658959: R634.2 U52.F19(TDO)
N19059235: J17.1(VREF_DBG) J17.12(VREF_TR) R758.2
N19060121: J17.15(TGT_DETECT) R762.2
N19188276: C3.1 P4.18(+5V) U1.12(5V_OUT)
N20370253: C477.1 U52.K9(CAP_VBBLDO_DSPEVE)
N20470386: C506.1 U52.Y15(CAP_VDDRAM_CORE3)
N20470388: C517.1 U52.J19(CAP_VDDRAM_CORE2)
N20470390: C516.1 U52.P19(CAP_VDDRAM_CORE4)
N20474519: C512.1 U52.Y16(CAP_VDDRAM_CORE5)
N21014314: C36.1 U9.17(REG_CAP2)
N21014318: C39.1 U9.19(REG_CAP1)
N21014360: C42.2 U9.21(XIN) Y2.1(Y1)
N21014402: R62.1 R63.2 U9.11(OS0)
N21014404: R64.2 R65.1 U9.10(OS1)
N21014459: TP6.1 U9.23(OSCOUT)
N21014498: R70.2 R71.1 U9.7(0E)
N21014569: C42.1 R75.1 Y2.3(C1)
N22623561: P7.B17(~{PRSNT2}) R439.2
N23034062: C123.2 C124.2 U52.AC14(VSSA_OSC1) Y5.2 Y5.4
N23034072: C106.1 U52.AD14(RTC_OSC_XO) Y3.1
N23034098: C113.1 U52.AE14(RTC_OSC_XI_CLKIN32) Y3.4
N23034254: C123.1 U52.AC15(XI_OSC1) Y5.1
N23034256: C124.1 U52.AC13(XO_OSC1) Y5.3
N23034287: C126.1 U52.AD15(X0_OSC0) Y6.2
N23034295: C128.1 U52.AE15(XI_OSC0) Y6.1
N23034297: C126.2 C128.2 U52.AF15(VSSA_OSC0)
N23239753: P7.A6(TDI) R416.2
N23239754: P7.A8(TMS) R415.2
N23239764: R420.1 U12.1(~{RESE}T) U16.1(~{RESE}T) U17.2(A)
N23239765: R98.2 R99.2 U12.5(SENSE1)
N23239774: C279.1 U12.4(CT)
N23239782: P7.A5(TCK) R421.1
N23239783: P7.B9(TRSTn) R448.1
N23239789: P7.A11(PERSTn) R413.1 RU13.4(O) U11.2(I)
N23239829: R104.2 R106.2 U16.5(SENSE1)
N23239838: C292.1 U16.4(CT)
N23239846: P7.A1(~{PRSNT1}) R439.1
N23239876: RU13.2(I) U17.4(Y)
N23587553: J5.33 R828.1 U144.4(O)
N25948424: U61.1(B) U62.4(Y)
N27151094: R269.1 U52.AF14(RTC_ISO)
N28915304: R653.2 U52.D24(EMU1)
N28915306: R627.2 U52.G21(EMU0)
N29820483: C462.1 U52.J9(CAP_VDDRAM_DSPEVE2)
N29820515: C468.1 U52.L9(CAP_VDDRAM_CORE1)
N29820517: C520.1 U52.K19(CAP_VDDRAM_MPU2)
N29829790: C519.1 U52.R20(CAP_VBBLDO_IVA)
N29829792: C501.1 U52.Y14(CAP_VBBLDO_GPU)
N29829794: C509.1 U52.J16(CAP_VBBLDO_MPU)
N29829846: C529.1 U52.T20(CAP_VDDRAM_IVA)
N29829848: C481.1 U52.J10(CAP_VDDRAM_DSPEVE1)
N29829850: C480.1 U52.Y13(CAP_VDDRAM_GPU)
N29829882: C504.1 U52.K16(CAP_VDDRAM_MPU1)
N32733566: R332.2 R333.1 U3.24(MODE_SEL)
N32742919: C235.1 C236.1 L3.2 U3.30(VDDIO)
N32792459: C229.1 C231.1 L2.1 U3.22(VDD33)
N32801911: C8.1 U3.14(CAPP12)
N32804282: C13.1 C234.1 U3.7(CAPL12)
N32806655: C7.1 U3.17(CAPHS12)
N32835273: C232.1 U3.23(CMF)
N32856854: C5.1 U3.20(DOUT+)
N32861613: C6.1 U3.19(DOUT-)
N32916975: R20.2 R338.1 U3.6(IDX)
N33052757: J5.27 R60.2
N33052765: J5.23 RN8.3(R3A)
N33052767: J5.24 RN8.4(R4A)
N33052820: J5.22 RN8.2(R2A)
N33052822: J5.21 RN8.1(R1A)
N33052958: J5.7 TP5.1
N33053022: J5.19 RN9.3(R3A)
N33053024: J5.20 RN9.4(R4A)
N33053026: J5.18 RN9.2(R2A)
N33053028: J5.17 RN9.1(R1A)
N33053058: J5.15 RN10.3(R3A)
N33053060: J5.16 RN10.4(R4A)
N33053062: J5.14 RN10.2(R2A)
N33053064: J5.13 RN10.1(R1A)
N33053104: J5.9 R58.2
N33053172: J5.11 R59.2
N33053182: J5.12 R353.2
N33053241: J5.28 R356.2
N33151523: R10.1 U3.11(I2S_DA/O6)
N33156530: R9.1 U3.12(I2S_WC/O7)
N33159038: R11.1 U3.13(I2S_CLK/O8)
N33161549: C228.1 R8.2 U3.21(PDB)
N45386793: TP40.1 U52.H7(VIN2A_FLD0)

Not connected (* = marked no-connect by the designer): J5 35*; J17 10(EXTE)* 11(EXTF)* 14(TR_CLK1)* 18(TRD1.0)* 20(TRD1.1)* 22(TRD1.2)* 24(TRD1.3)* 26(TRD1.4)* 28(TRD1.5)* 30(TRD1.6)* 32(TRD1.7)* 34(TRD1.8)* 36(TRD1.9)* 38(TRD2.0)* 40(TRD2.1)* 42(TRD2.2)* 44(TRD2.3)* 46(TRD2.4)* 48(TRD2.5)* 50(TRD2.6)* 52(TRD2.7)* 54(TRD2.8)* 55(TRD3.9)* 56(TRD2.9)* 59(TR_CLK3)* 60(TR_CLK2)*; MHC1 1(TP); MHC2 1(TP); P4 14(NC.14)*; P7 A7(TDO)* B5(SMCLK)* B6(SMDAT)* B10(3.3VAUX)* B11(WAKEn)* B12(RSVD.1)*; RU19 3(1B2) 6(2B2) 10(3B2) 13(4B2); RU30 30(12B1) 32(11B1) 34(10B1) 36(9B1) 39(8B1) 41(7B1) 43(6B1) 45(5B1) 47(4B1) 50(3B1) 52(2B1) 54(1B1); RU31 29(12B2) 31(11B2) 33(10B2) 35(9B2) 37(8B2) 40(7B2) 42(6B2) 44(5B2) 46(4B2) 48(3B2); RU93 3(1B3) 5(2B3) 7(3B3) 10(4B3) 12(5B3) 14(6B3) 16(7B3) 20(8B3) 22(9B3) 24(10B3) 26(11B3) 28(12B3); U1 14(CLK-) 15(CLK+) 16(D0-) 17(D0+) 19(D1-) 20(D1+) 21(D2-) 22(D2+); U3 16(NC.16); U9 8(NC.8) 13(NC.13) 15(NC.15) 24(NC.24) 25(NC.25) 26(NC.26) 27(NC.27) 28(NC.28) 29(NC.29) 30(NC.30) 31(NC.31) 32(NC.32); U12 3(~{MR})*; U16 3(~{MR})*; U25 1(NC1); U26 1(NC1)

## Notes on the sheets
sheet 23
- vin2a_d[12]
  vin2a_d[13]
  vin2a_d[14]
  vin2a_d[15]
  vin2a_d[16]
  vin2a_d[17]
  vin2a_d[18]
  vin2a_d[19]
  vin2a_d[20]
  vin2a_d[21]
  vin2a_d[22]
  vin2a_d[23]
- rgmii1_txc
  rgmii1_txctl
  rgmii1_txd[3]
  rgmii1_txd[2]
  rgmii1_txd[1]
  rgmii1_txd[0]
  rgmii1_rxc
  rgmii1_rxctl
  rgmii1_rxd[3]
  rgmii1_rxd[2]
  rgmii1_rxd[1]
  rgmii1_rxd[0]
sheet 24
- This will allow testing of the ACTVID style of
  capture with the sensor.   Add 0 Ohm series
  resistor between U24 pin 6 and CAMERA_HSYNC
  signal.
   Add no-pop resistor between CAMERA_HSYNC
  signal and U24 pin 3 ( enables routing
  CAMERA_HSYNC to VIN[1]A_DE0)."
sheet 25
- FUNCTION TABLE
  INPUTS      INPUTS/OUTPUTS        FUNCTION
  S2 S1 S0          A1 A2
  L L L             Z Z               Disconnect
  L L H             B1 Z          A1 port = B1 port
  L H L             B2 Z          A1 port = B2 port
  L H H             Z B1          A2 port = B1 port
  H L L             Z B2          A2 port = B2 port
  H L H             Z Z           Disconnect
  H H L             B1 B2         A1 port = B1 port
                                  A2 port = B2 port
  H H H             B2 B1         A1 port = B2 port
                                  A2 port = B1 port
- FUNCTION TABLE
  INPUTS      INPUTS/OUTPUTS        FUNCTION
  S2 S1 S0          A
  L L L             Z                Disconnect
  L L H             B1          A port = B1 port
  L H L             B2          A port = B2 port
  L H H             Z             Disconnect
  H L L             Z              Disconnect
  H L H             B3          A port = B3 port
  H H L             B1          A port = B1 port
  H H H             B2          A port = B2 port
- vin2a_d[12]
  vin2a_d[13]
  vin2a_d[14]
  vin2a_d[15]
  vin2a_d[16]
  vin2a_d[17]
  vin2a_d[18]
  vin2a_d[19]
  vin2a_d[20]
  vin2a_d[21]
  vin2a_d[22]
  vin2a_d[23]
- rgmii1_txc
  rgmii1_txctl
  rgmii1_txd[3]
  rgmii1_txd[2]
  rgmii1_txd[1]
  rgmii1_txd[0]
  rgmii1_rxc
  rgmii1_rxctl
  rgmii1_rxd[3]
  rgmii1_rxd[2]
  rgmii1_rxd[1]
  rgmii1_rxd[0]
sheet 27
- DIFFERENTIAL PAIR
  100 OHM DIFFERENTIAL
  IMPEDANCE
  SHORT AND STRAIGHT AS
  POSSIBLE,
  MINIMUM NUMBER OF VIAS
- DIFFERENTIAL PAIR
  100 OHM DIFFERENTIAL
  IMPEDANCE
  SHORT AND STRAIGHT AS
  POSSIBLE,
  MINIMUM NUMBER OF VIAS
- ER13
- REV G
- THE HDMI I2C SIGNALS ARE
  CROSSED IN VAYU AND NEED TO BE
  UNCROSSED AT THE BOARD LEVEL.
  THIS UNCROSS IS MOVED TO RU108
  ON SHEET 5, REVE.
- REVE
sheet 28
- VOUT3 INTERFACE
- TRANSMIT USES 1 DATA - 3 DATA +
- REV E
sheet 29
- THESE TERMINATIONS ON CAMERA MAY NOT BE
  NEEDED. THE CAMERA SCHEMATIC APPEARS TO
  HAVE SOURCE TERMS ON BOARD.
- REV G
sheet 30
- DIFFERENTIAL PAIR
  100 OHM DIFFERENTIAL
  IMPEDANCE
  SHORT AND STRAIGHT AS
  POSSIBLE,
  MINIMUM NUMBER OF VIAS
- LVDS OUTPUT
  OSCOUT PIN = OFF
- CE = '1' = ON
- OUTCLOCK = 100mHZ
sheet 31
- Reset Threhold 0.84 Volts
- Reset Threhold 0.84 Volts
- Connector must be less than 2.25 inches
  to board edge from key to board edge
sheet 32
- ER52
- ER42
- TRSTn ==  MIPI TRSTPD PULL DOWN VERSION
  TRSTn ==  MIPI nTRST MIPI PULLUP VERSION
  FOR CJTAG REMOVE R761 AND POPULATE R760,
  AS CTJAG NEEDS THE PULLUP VERSION.
- EMUx SIGNALS NEED TO ROUTE FROM U52
  THROUGH J17/J14 THEN TO LCD.  THE TRACE
  LENGTH RULES FOR THE LCD SIGNALS NEEDS
  TO BE MAINTAINED.
sheet 33
- ER8
- REV G2
- ON_OFF = 1 COMMANDS ALL NON-RTC DOMAINS TO BE ACTIVE
  ON_OFF = 0 COMMANDS ALL NON-RTC DOMAINS TO BE IN-ACTIVE
- Note: WAKEUP[3:0], including the
  GP1[x] functions, are
  input-only.
- ER14
- REV D. OPEN DRAIN FROM PMIC VIA FET
- ON RTC POWER DOMAIN
- ON RTC POWER DOMAIN
